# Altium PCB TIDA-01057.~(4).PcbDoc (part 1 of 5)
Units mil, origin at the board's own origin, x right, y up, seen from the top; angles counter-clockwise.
Board outline 4448 x 3930 mil, 4 copper layers (Layer 1 - Top Layer, Layer 2 - GND, Layer 3 - PWR, Layer 4 - Bottom Layer), stack 59.034 mil thick; 537 components, 284 nets, 1540 pads, 770 vias.
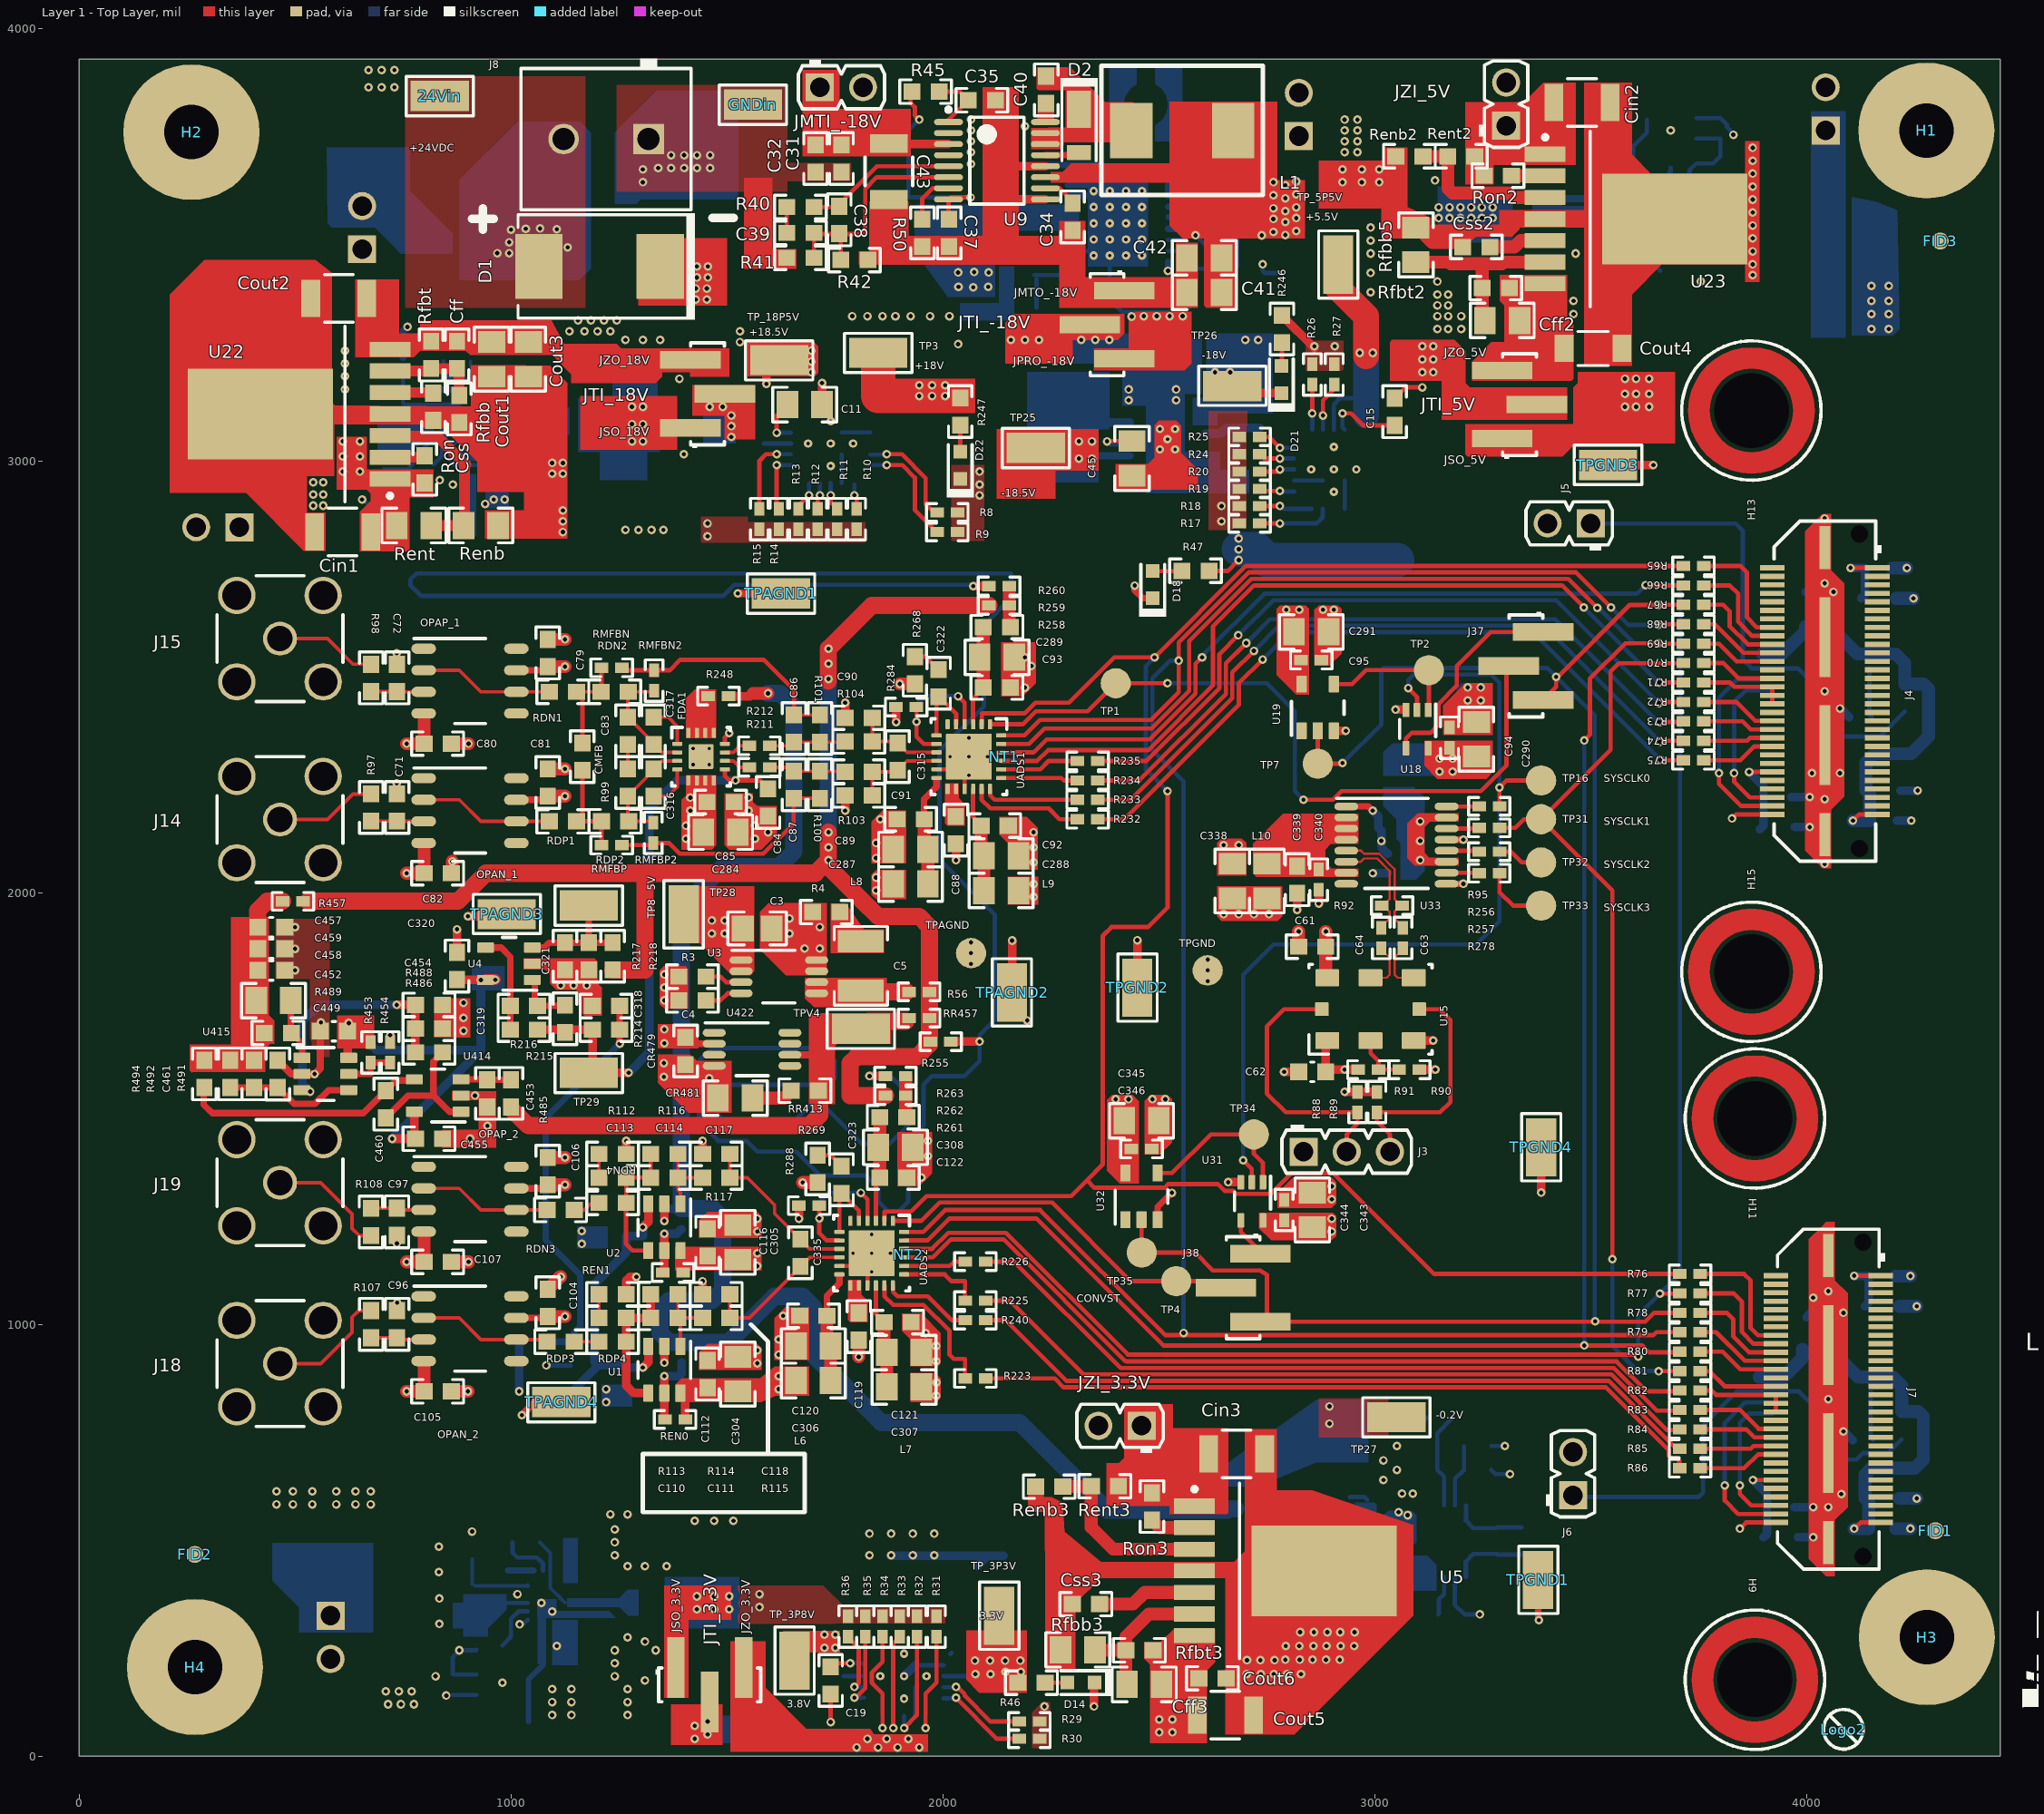
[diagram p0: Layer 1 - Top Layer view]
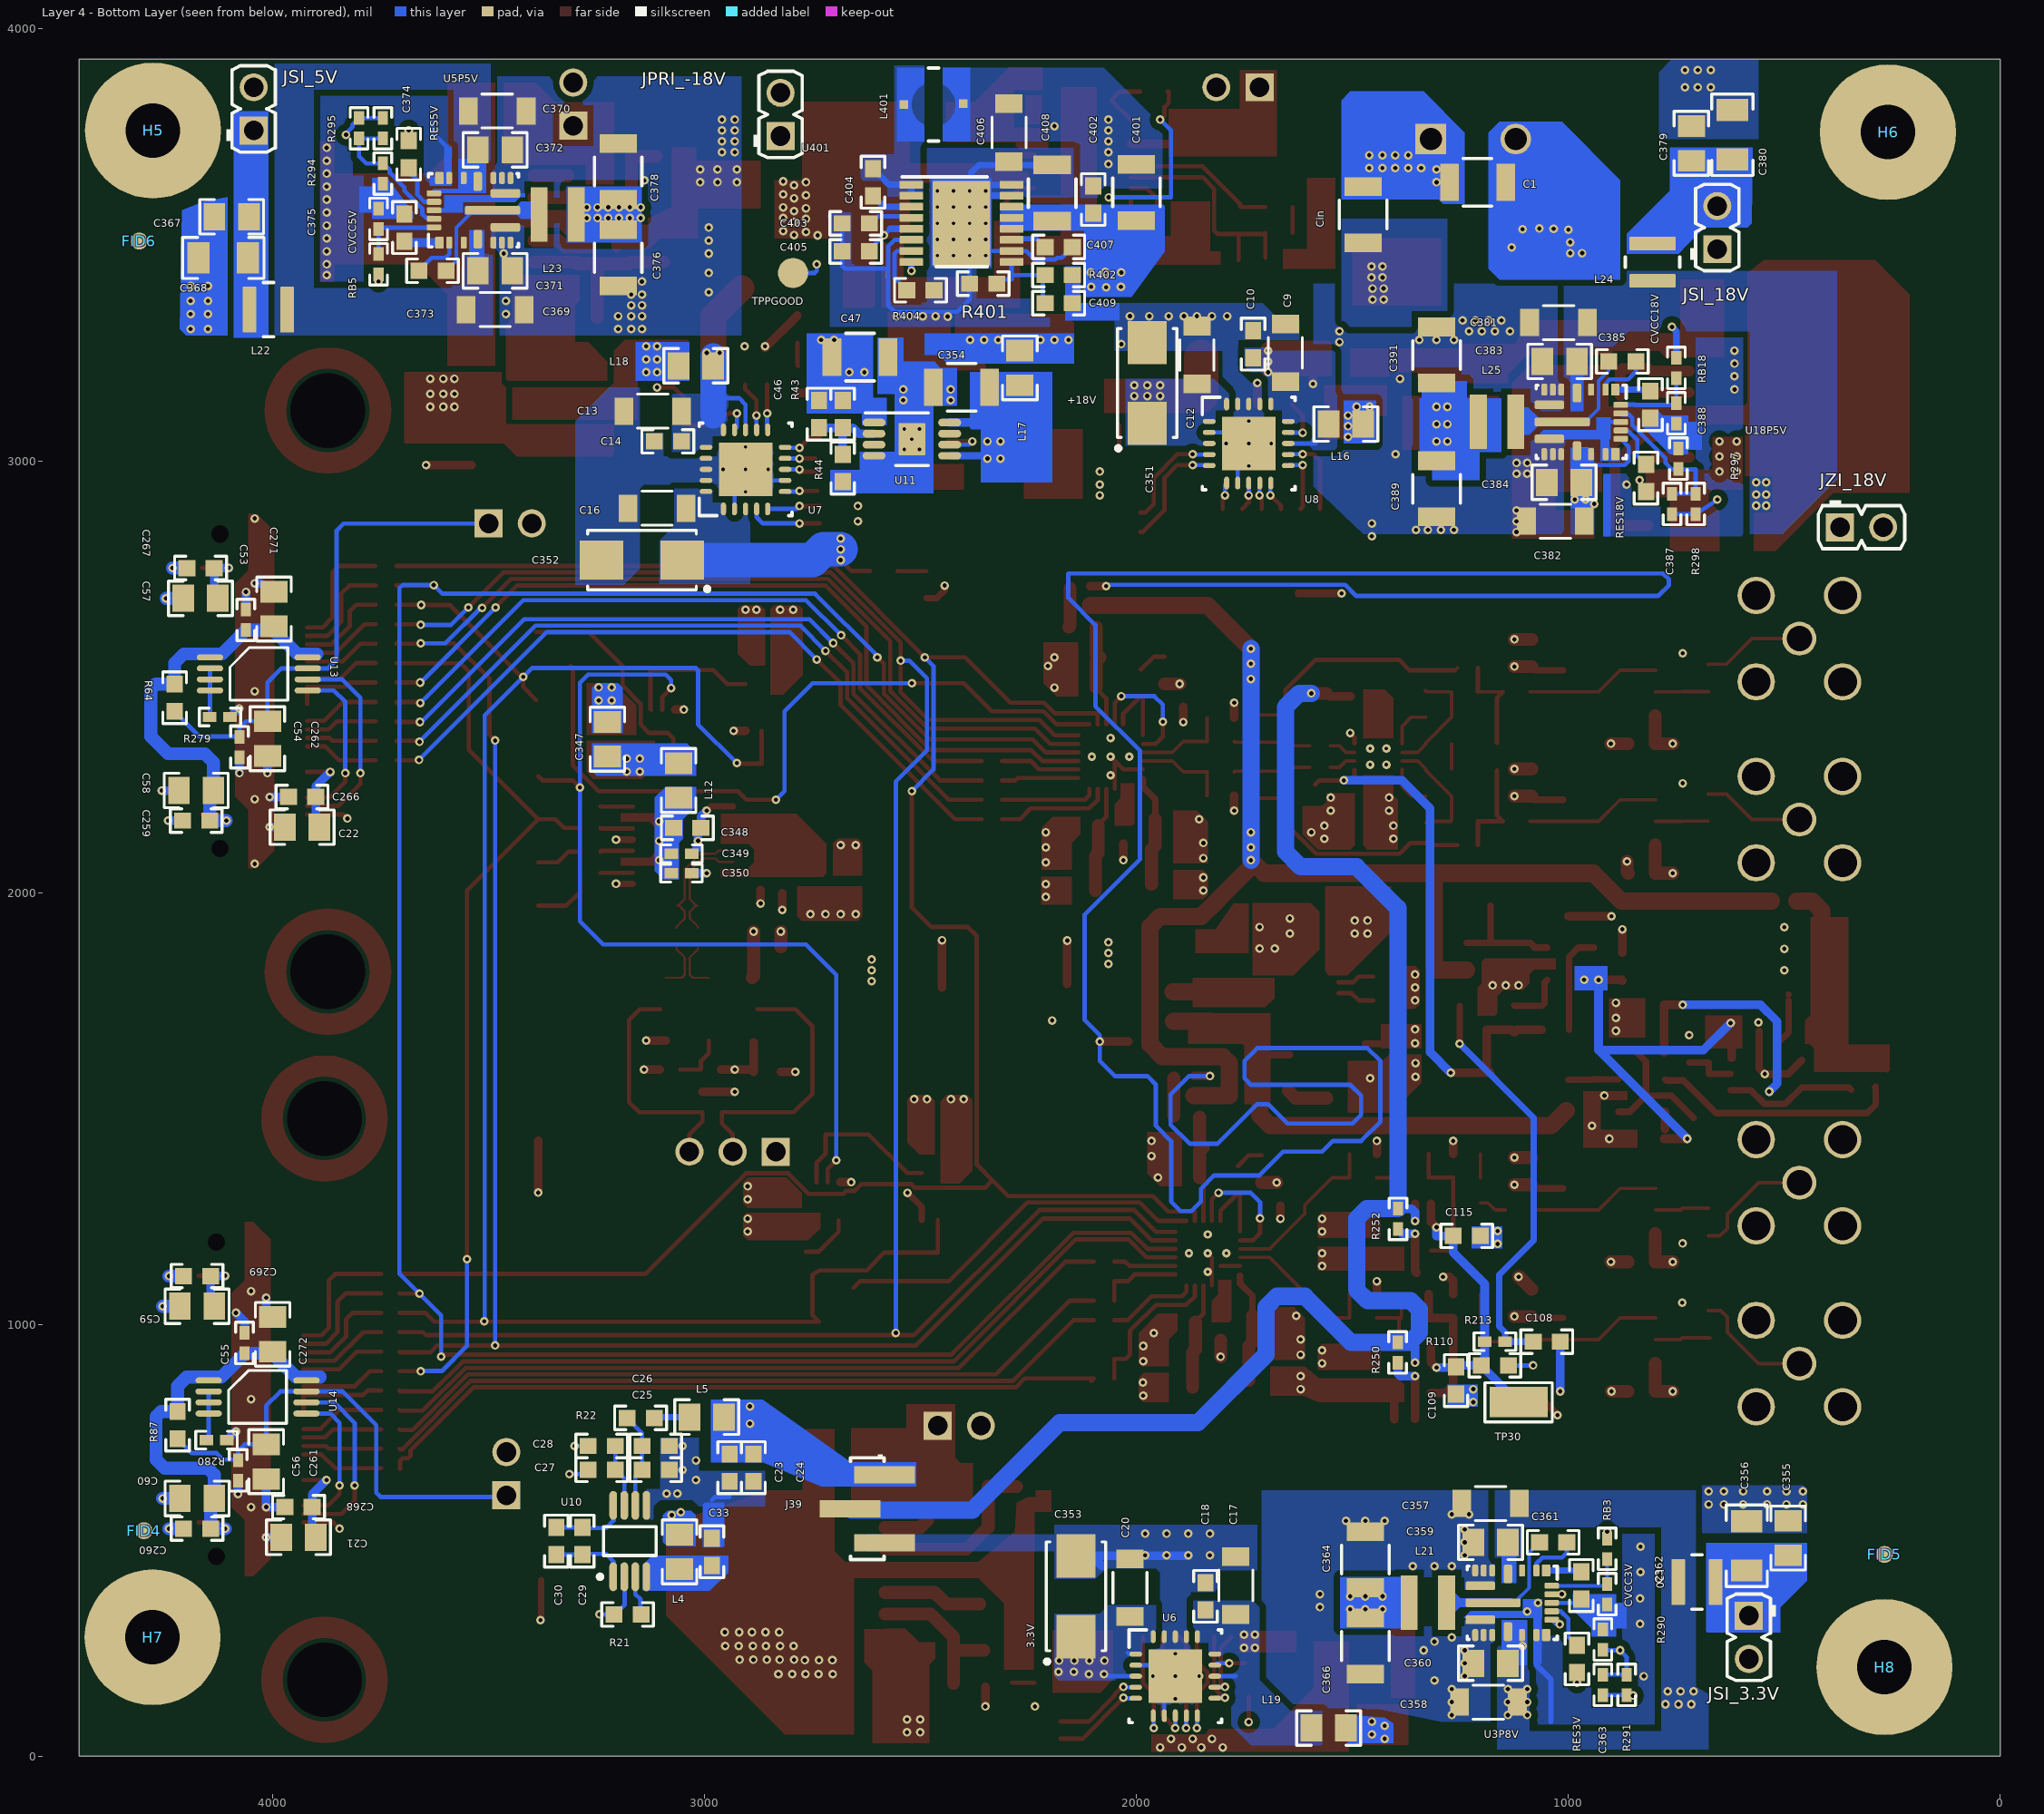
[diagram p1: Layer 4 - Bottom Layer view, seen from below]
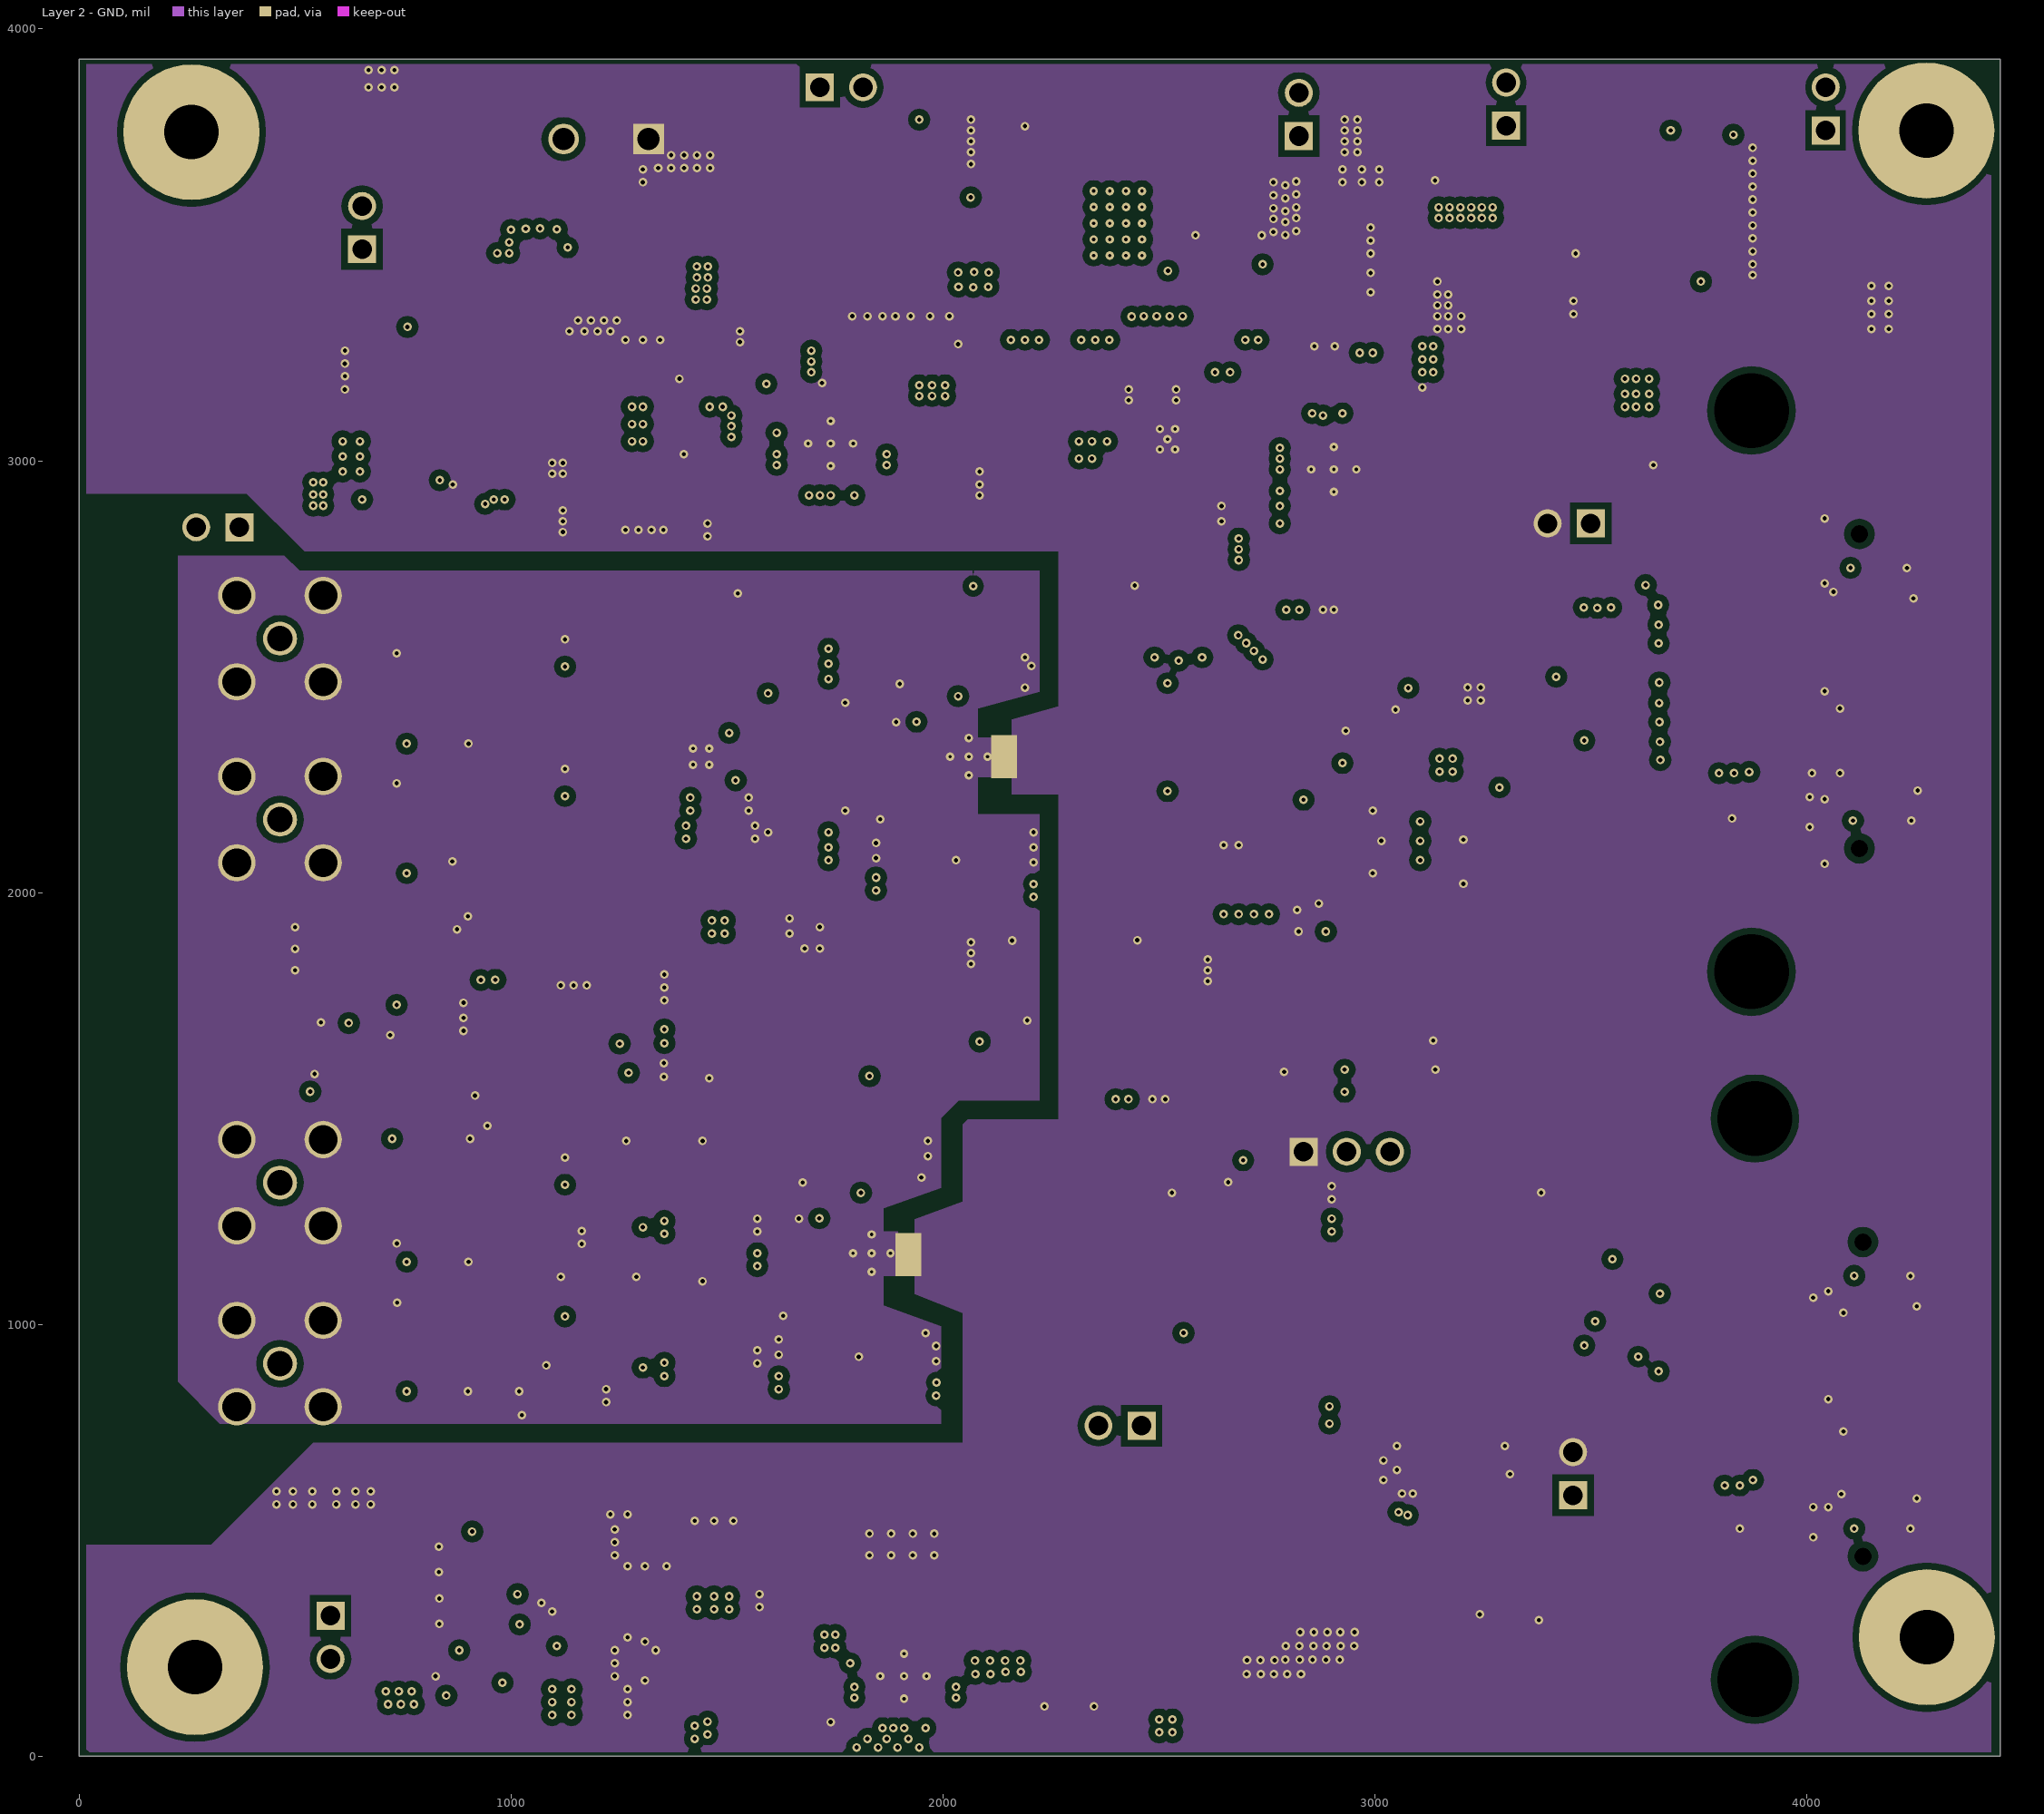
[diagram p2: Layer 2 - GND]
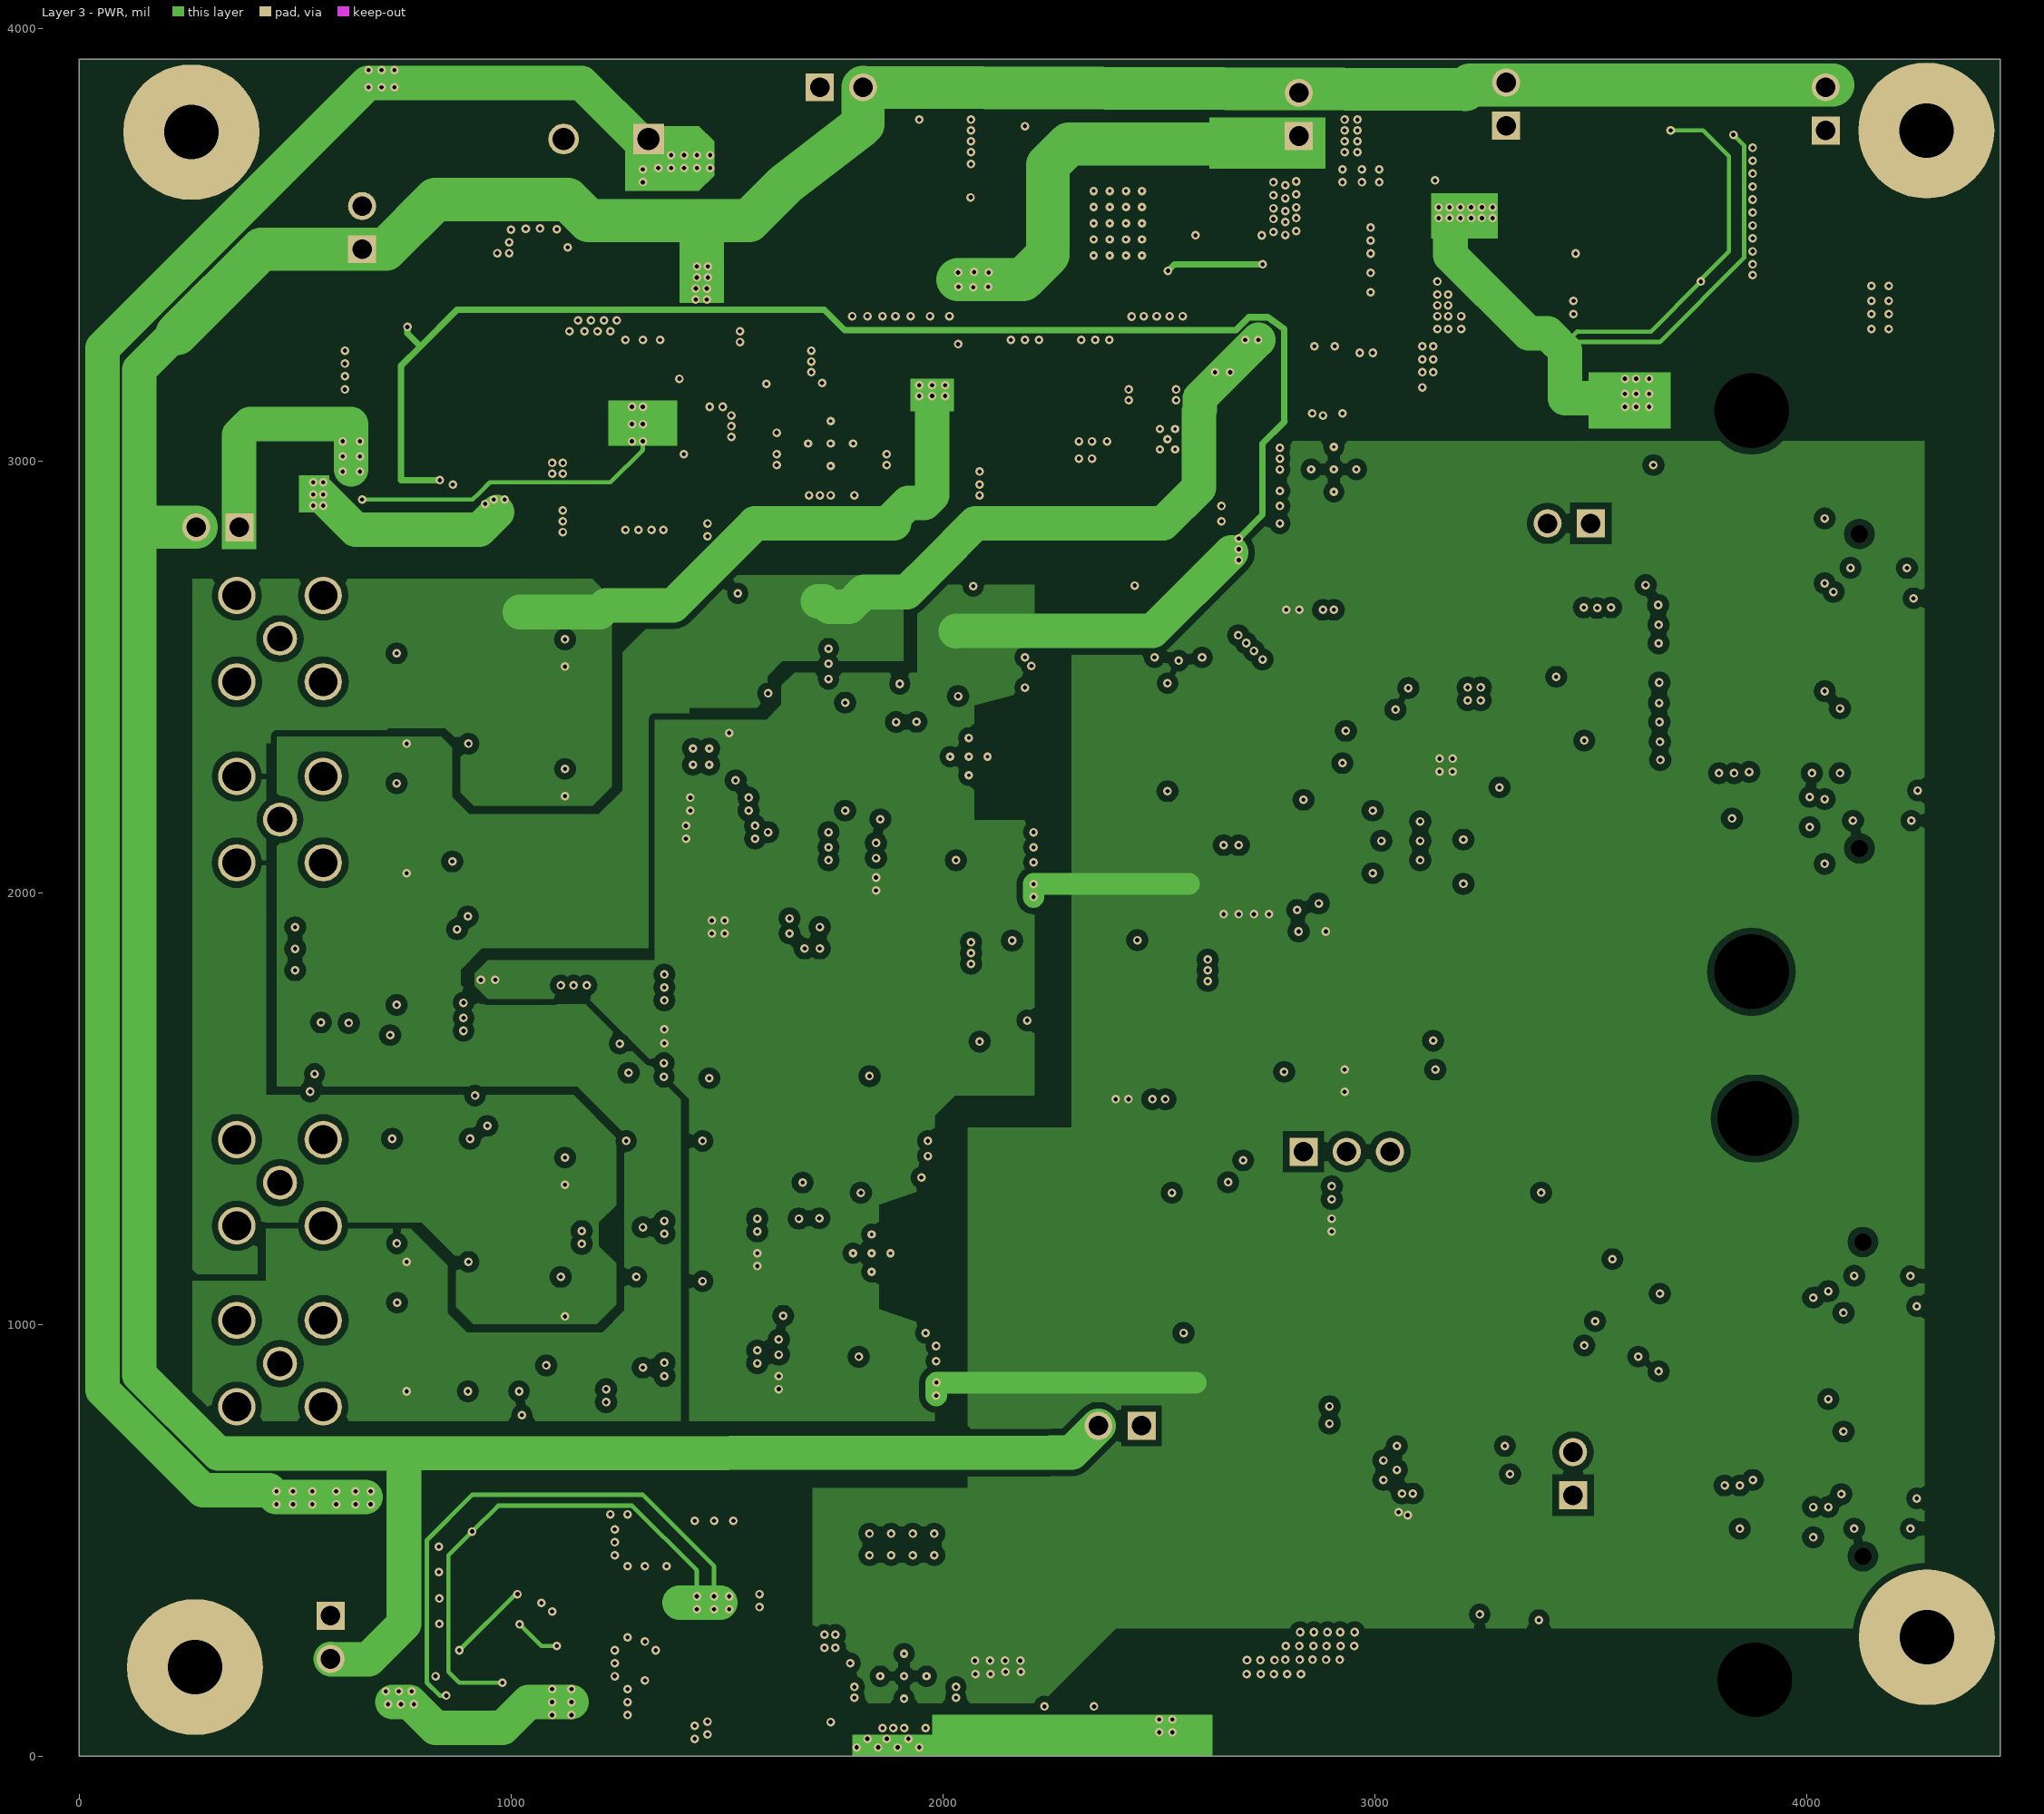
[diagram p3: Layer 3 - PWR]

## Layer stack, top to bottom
Top Solder: solder mask 0.4, Solder Resist, Dk 3.5
Layer 1 - Top Layer: signal copper 1.4
Dielectric 1: prepreg 5.2, 370HR, Dk 4.2
Layer 2 - GND: signal copper 1.417
Dielectric 2: core 43, 370HR, Dk 4.2
Layer 3 - PWR: signal copper 1.417
Dielectric 3: prepreg 5.2, 370HR, Dk 4.2
Layer 4 - Bottom Layer: signal copper 1.4
Bottom Solder: solder mask 0.4, Solder Resist, Dk 3.5

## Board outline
0,0 0,3930 4448,3930 4448,0

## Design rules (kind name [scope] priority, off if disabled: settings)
AcuteAngle [All] p1: minimum=4.50000000000000E+0001 checktracksonly=FALSE
AssemblyTestPointUsage [All] p1: valid=2
Clearance Clearance_Keepouts [((IsTrack Or IsArc) And Not InPoly) And IsFree and IsKeepOut vs ((IsTrack Or IsArc) And Not InPoly) And IsFree and IsKeepOut] p1: gap=0 ignorepadtopadclearanceinfootprint=FALSE
Clearance Clearance_BoardEdge_MountingHoles [OnCopper and InComponentClass('Mounting Holes') vs IsKeepOut] p2: gap=40 ignorepadtopadclearanceinfootprint=FALSE except(0: Arc-Hole Track-Hole SMDPad-Hole THPad-Hole Via-Hole Fill-Hole Poly-Hole Region-Hole Text-Hole)
Clearance Clearance_BoardEdge_Poly [OnCopper and InPoly vs IsKeepOut] p3: gap=25 ignorepadtopadclearanceinfootprint=FALSE except(0: Arc-Hole Track-Hole SMDPad-Hole THPad-Hole Via-Hole Fill-Hole Poly-Hole Region-Hole Text-Hole)
Clearance Clearance_BoardEdge [OnCopper and Not InComponentClass('Logo') and not InComponentClass('FiducialMark') and not InRegion(1000,500,4000,800) and Not IsKeepout vs IsKeepOut] p4: gap=75 ignorepadtopadclearanceinfootprint=FALSE except(0: Arc-Hole Track-Hole SMDPad-Hole THPad-Hole Via-Hole Fill-Hole Poly-Hole Region-Hole Text-Hole)
Clearance Clearance_Poly [InPolygon] p5: gap=15 ignorepadtopadclearanceinfootprint=FALSE except(0: Arc-Hole Track-Hole SMDPad-Hole THPad-Hole Via-Hole Fill-Hole Poly-Hole Region-Hole Text-Hole)
Clearance [All] p6: gap=5 ignorepadtopadclearanceinfootprint=FALSE except(0: Arc-Hole Track-Hole SMDPad-Hole THPad-Hole Via-Hole Fill-Hole Poly-Hole Region-Hole Text-Hole)
ComponentClearance ComponentClearance_MountingHoles_FiducialMarks [InComponentClass('Mounting Holes') vs InComponentClass('FiducialMark')] p1: gap=25 collisioncheckmode=3 verticalgap=10 showdistances=FALSE
ComponentClearance ComponentClearance_Shunt [InComponentClass('Header') vs InComponentClass('Shunt')] p2: gap=0 collisioncheckmode=3 verticalgap=0 showdistances=FALSE
ComponentClearance ComponentClearance_Logo [InComponentClass('Logo')] p3: gap=10 collisioncheckmode=3 verticalgap=10 showdistances=FALSE
ComponentClearance ComponentClearance_ScrewToNut [(HasFootprint('NY PMS 440 0025 PH')) vs (HasFootprint('Keystone_1902C'))] p4: gap=5 collisioncheckmode=3 verticalgap=10 showdistances=FALSE
ComponentClearance ComponentClearance_MountingHoles [InComponentClass('Mounting Holes')] p5: gap=15 collisioncheckmode=3 verticalgap=100000 showdistances=FALSE
ComponentClearance ComponentClearance_SmallPassives [HasFootprint('0201*') or HasFootprint('0402*') or HasFootprint('0508') or HasFootprint('0603*') or HasFootprint('0612') or HasFootprint('0805*') or HasFootprint('0815*') or HasFootprint('0830*') or HasFootprint('1206*') or HasFootprint('1210*') or HasFootprint('1808*') or HasFootprint('1812*') or HasFootprint('1825*') or HasFootprint('2010*') or HasFootprint('2220*') or HasFootprint('2225*') or HasFootprint('2512*') or HasFootprint('2728*') or HasFootprint('3518*') vs HasFootprint('0201*') or HasFootprint('0402*') or HasFootprint('0508') or HasFootprint('0603*') or HasFootprint('0612') or HasFootprint('0805*') or HasFootprint('0815*') or HasFootprint('0830*') or HasFootprint('1206*') or HasFootprint('1210*') or HasFootprint('1808*') or HasFootprint('1812*') or HasFootprint('1825*') or HasFootprint('2010*') or HasFootprint('2220*') or HasFootprint('2225*') or HasFootprint('2512*') or HasFootprint('2728*') or HasFootprint('3518*')] p6: gap=5 collisioncheckmode=3 verticalgap=10 showdistances=FALSE
ComponentClearance ComponentClearance_THtoSMT [IsThruComponent vs IsSMTComponent] p7: gap=10 collisioncheckmode=3 verticalgap=30 showdistances=FALSE
ComponentClearance ComponentClearance_THtoTH [IsThruComponent vs IsThruComponent] p8: gap=75 collisioncheckmode=3 verticalgap=30 showdistances=FALSE
ComponentClearance [All] p9: gap=5 collisioncheckmode=3 verticalgap=10 showdistances=FALSE
DiffPairsRouting [All] p1: maxlimit=20 minlimit=6 mostfreqgap=6 toplayer_minwidth=5 toplayer_maxwidth=5 toplayer_prefwidth=5 midlayer1_minwidth=5 midlayer1_maxwidth=5 midlayer1_prefwidth=5 midlayer2_minwidth=5 midlayer2_maxwidth=5 midlayer2_prefwidth=5 bottomlayer_minwidth=5 bottomlayer_maxwidth=5 bottomlayer_prefwidth=5 maxuncoupledlength=1000
FabricationTestPointUsage TestPointUsage [All] p1: valid=2 allowmultiple=FALSE
FabricationTestpoint Testpoint [All] p1: side=3 testpointundercomponent=TRUE minsize=40 maxsize=100 preferedsize=60 minholesize=0 maxholesize=40 preferedholesize=32 testpointgrid=1 allowsidetop=TRUE allowsidebottom=TRUE usegrid=TRUE gridtolerance=0.01
FanoutControl Fanout_LCC [IsLCC] p1: bgadir=Out bgaviamode=Centered fanoutstyle=Auto fanoutdirection=Alternating viagrid=1 // Fanout_LCC (Default Rule)
FanoutControl Fanout_BGA [IsBGA] p2: bgadir=Out bgaviamode=Centered fanoutstyle=Auto fanoutdirection=Alternating viagrid=1 // Fanout_BGA (Default Rule)
FanoutControl Fanout_Default [All] p4: bgadir=Out bgaviamode=Centered fanoutstyle=Auto fanoutdirection=Alternating viagrid=1 // Fanout_Default (Default Rule)
FanoutControl Fanout_Small [(CompPinCount < 5)] p5: bgadir=Out bgaviamode=Centered fanoutstyle=Auto fanoutdirection=OutThenIn viagrid=1 // Fanout_Small (Default Rule)
HoleSize [All] p1: absolutevalues=TRUE maxlimit=251 minlimit=6 maxpercent=80.000 minpercent=20.000
MinimumAnnularRing MinimumAnnularRing_ThermalPadVias [IsVia and InAnyComponent] p1: minimumring=5.91
MinimumAnnularRing [All] p2: minimumring=5
MinimumSolderMaskSliver MinimumSolderMaskSliver_Logo [InComponentClass('Logo') vs InComponentClass('Logo')] p1: minsoldermaskwidth=0
MinimumSolderMaskSliver [All] p2: minsoldermaskwidth=0
PlaneConnect [All] p1: planeconnectstyle=Direct reliefexpansion=10 reliefentries=4 reliefconductorwidth=10 reliefairgap=10
PolygonConnect PolygonConnect_1 [All vs IsNamedPolygon('AGND_L02_P018')] p1: connectstyle=Direct reliefconductorwidth=10 reliefentries=4 polygonreliefangle="90 Angle" airgapwidth=10
PolygonConnect [All] p2: connectstyle=Direct reliefconductorwidth=10 reliefentries=4 polygonreliefangle="90 Angle" airgapwidth=10
RoutingVias ThermalPadVias [IsVia and InAnyComponent] p1: holewidth=7.87 width=19.68 viastyle="Through Hole" minholewidth=7.87 minwidth=19.68 maxholewidth=12.99 maxwidth=23.62
RoutingVias [All] p2: holewidth=16 width=34 viastyle="Through Hole" minholewidth=7.87 minwidth=20 maxholewidth=40 maxwidth=65
SilkToBoardRegionClearance [Not ((IsComment or IsDesignator) And (Hide <> 'False')) and not InRegion(1000,500,4000,800)] p1:
SilkToSilkClearance SilkToSilkClearance_Pb-FreeLogo [(HasFootprint('Pb-Free_Overlay_Medium') OR HasFootprint('Pb-Free_Overlay_Small')) vs (HasFootprint('Pb-Free_Overlay_Medium') OR HasFootprint('Pb-Free_Overlay_Small'))] p1: silktosilkclearance=0
SilkToSilkClearance [All] p2: silktosilkclearance=0
SilkToSolderMaskClearance SilkToComonentPadClearance [IsPad and InAnycomponent] p1: minsilkscreentomaskgap=0 clearancetoexposedcopper=TRUE
SilkToSolderMaskClearance "Silk to Solder Mask Opening" [All] p2: minsilkscreentomaskgap=0 clearancetoexposedcopper=FALSE
SolderMaskExpansion [All] p1: expansion=1.97
Width Width_DA1_N [InNet('DA1_N')] p1: maxlimit=10 minlimit=5 preferedwidth=5 impedancedriven=TRUE minimp=50.000000 maximp=50.000000 favimp=50.000000
Width Width_DA2_N [InNet('DA2_N')] p2: maxlimit=10 minlimit=5 preferedwidth=5 impedancedriven=TRUE minimp=50.000000 maximp=50.000000 favimp=50.000000
Width Width_DA1_P [InNet('DA1_P')] p3: maxlimit=10 minlimit=5 preferedwidth=5 impedancedriven=TRUE minimp=50.000000 maximp=50.000000 favimp=50.000000
Width Width_DA2_P [InNet('DA2_P')] p4: maxlimit=10 minlimit=5 preferedwidth=5 impedancedriven=TRUE minimp=50.000000 maximp=50.000000 favimp=50.000000
Width Width_VIN+1_P [InNet('VIN+_1_P')] p5: maxlimit=10 minlimit=5 preferedwidth=5 impedancedriven=TRUE minimp=50.000000 maximp=50.000000 favimp=50.000000
Width Width_VIN+2_N [InNet('VIN+_2_N')] p6: maxlimit=10 minlimit=5 preferedwidth=5 impedancedriven=TRUE minimp=50.000000 maximp=50.000000 favimp=50.000000
Width Width_VIN+2_P [InNet('VIN+_2_P')] p7: maxlimit=10 minlimit=5 preferedwidth=5 impedancedriven=TRUE minimp=50.000000 maximp=50.000000 favimp=50.000000
Width Width_VIN+1_N [InNet('VIN+_1_N')] p8: maxlimit=10 minlimit=5 preferedwidth=5 impedancedriven=TRUE minimp=50.000000 maximp=50.000000 favimp=50.000000
Width [All] p9: maxlimit=100 minlimit=5 preferedwidth=10 checkconnectedcopper=TRUE
15 further rules are at their usual default settings.

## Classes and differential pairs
component class "OPA625 ADC Driver_Power_1050": C31 C32 C34 C35 C37 C38 C39 C40 C41 C42 C43 Cff Cff2 Cff3 Cin1 Cin2 Cin3 Cout1 Cout2 Cout3 Cout4 Cout5 Cout6 Css Css2 Css3 D2 JMTI_-18V JZI_3.3V JZI_5V JZI_18V L1 R40 R41 R42 R45 R50 Renb Renb2 Renb3 Rent Rent2 Rent3 Rfbb Rfbb3 Rfbb5 Rfbt Rfbt2 Rfbt3 Ron Ron2 Ron3 U5 U9 U22 U23
component class AssemblyNote: ZZ2 ZZ3 ZZ4
component class FiducialMark: FID1 FID2 FID3 FID4 FID5 FID6
component class "OPA625 ADC Driver_Hardware": FID1 FID2 FID3 FID4 FID5 FID6 H1 H2 H3 H4 H5 H6 H7 H8 H9 H11 H13 H15 Logo1 Logo2 ZZ2 ZZ3 ZZ4
component class Logo: Logo1
component class "Mounting Holes": H1 H2 H3 H4
component class Header: J3 J5 J6 J37 J38 J39 JMTI_-18V JPRI_-18V JSI_3.3V JSI_5V JSI_18V JTI_3.3V JTI_5V JTI_18V JTI_-18V JZI_3.3V JZI_5V JZI_18V
component class "OPA625 ADC Driver_Clock": C61 C62 C63 C64 C338 C339 C340 C347 C348 C349 C350 J3 L10 L12 R88 R89 R90 R91 R92 R95 R256 R257 R278 TP16 TP31 TP32 TP33 U15 U33
component class "OPA625 ADC Driver_Connectors": C21 C22 C53 C54 C55 C56 C57 C58 C59 C60 C259 C260 C261 C262 C266 C267 C268 C269 C271 C272 J4 J5 J6 J7 R64 R65 R66 R67 R68 R69 R70 R71 R72 R73 R74 R75 R76 R77 R78 R79 R80 R81 R82 R83 R84 R85 R86 R87 R279 R280 U13 U14
component class "OPA625 ADC Driver_OPA625 ADC Driver REV1.0": C3 C4 C5 C71 C72 C79 C80 C81 C82 C83 C84 C85 C86 C87 C88 C89 C90 C91 C92 C93 C94 C95 C96 C97 C104 C105 C106 C107 C108 C109 C110 C111 C112 C113 C114 C115 C116 C117 C118 C119 C120 C121 C122 C284 C287 C288 C289 C290 C291 C304 C305 C306 C307 C308 C315 C316 C317 C318 C319 C320 C321 C322 C323 C335 C343 C344 C345 C346 C449 C452 C453 C454 C455 C457 C458 C459 C460 C461 CMFB CR479 CR481 FDA1 J14 J15 J18 J19 J37 J38 L6 L7 L8 L9 OPAN_1 OPAN_2 OPAP_1 OPAP_2 R3 R4 R56 R97 R98 R99 R100 R101 R103 R104 R107 R108 R110 R112 R113 R114 R115 R116 R117 R211 R212 R213 R214 R215 R216 R217 R218 R223 R225 R226 R232 R233 R234 R235 R240 R248 R250 R252 R255 R258 R259 R260 R261 R262 R263 R268 R269 R284 R288 R453 R454 R457 R485 R486 R488 R489 R491 R492 R494 RDN1 RDN2 RDN3 RDN4 RDP1 RDP2 RDP3 RDP4 REN0 REN1 RMFBN RMFBN2 RMFBP RMFBP2 RR413 RR457 TP1 Tp2 TP4 TP7 TP28 TP29 TP30 TP34 TP35 TPAGND TPV4 U1 U2 U3 U4 U18 U19 U31 U32 U414 U415 U422 UADS1 UADS2
component class "OPA625 ADC Driver_Power_1051": 24Vin C1 C9 C10 C11 C12 C13 C14 C15 C16 C17 C18 C19 C20 C23 C24 C25 C26 C27 C28 C29 C30 C33 C45 C46 C47 C351 C352 C353 C354 C355 C356 C357 C358 C359 C360 C361 C362 C363 C364 C366 C367 C368 C369 C370 C371 C372 C373 C374 C375 C376 C378 C379 C380 C381 C382 C383 C384 C385 C387 C388 C389 C391 C401 C402 C403 C404 C405 C406 C407 C408 C409 Cin CVCC3V CVCC5V CVCC18V D1 D14 D18 D21 D22 GNDin J8 J39 JPRI_-18V JSI_3.3V JSI_5V JSI_18V JTI_3.3V JTI_5V JTI_18V JTI_-18V L4 L5 L16 L17 L18 L19 L20 L21 L22 L23 L24 L25 L401 NT1 NT2 R8 R9 R10 R11 R12 R13 R14 R15 R17 R18 R19 R20 R21 R22 R24 R25 R26 R27 R29 R30 R31 R32 R33 R34 R35 R36 R43 R44 R46 R47 R246 R247 R290 R291 R294 R295 R297 R298 R401 R402 R404 RB3 RB5 RB18 RES3V RES5V RES18V TP3 TP8 TP25 TP26 Tp27 TP_3P3V TP_3P8V TP_5P5V TP_18P5V TPAGND1 TPAGND2 TPAGND3 TPAGND4 TPGND TPGND1 TPGND2 TPGND3 TPGND4 TPPGOOD U3P8V U5P5V U6 U7 U8 U10 U11 U18P5V U401
differential pair BCLK0: +BCLK0_P -BCLK0_N
differential pair BCLK1: +BCLK1_P -BCLK1_N

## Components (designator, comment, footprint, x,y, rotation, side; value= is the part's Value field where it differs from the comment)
24Vin "5015" Testpoint_Keystone_Miniature 835,3845 r0 top
C1 "UMK325AB7106KM-T" 1210_280 1210,3645 r0 bottom value=10uF
C3 "GRM21BR71A106KE51L" 0805 1569.79,1916.65 r180 top value=10uF
C4 "GRM188R71A105KA61D" 0603 1420,1750.16 r180 top value=1uF
C5 "GRM32ER71A476KE15L" 1210_270 1810,1830.16 r90 top value=47uF
C9 "C3216X5R1E476M160AC" 1206_190 1655,3250 r90 bottom value=47uF
C10 "CGA3E2X7R2A102K080AA" 0603 1730,3270 r90 bottom value=1000pF
C11 "C2012X7S2A105K125AB" 0805_HV 1680,3130 r0 top value=1uF
C12 "C3216X5R1E476M160AC" 1206_190 1860,3245 r90 bottom value=47uF
C13 "C3216X5R1E476M160AC" 1206_190 3120,3115 r0 bottom value=47uF
C14 "GRM1885C1H102FA01J" 0603 3085,3045 r0 bottom value=1000pF
C15 "GRM188R71E105KA12D" 0603 3046.02,3113.66 r270 top value=1uF
C16 "C3216X5R1E476M160AC" 1206_190 3110,2890 r0 bottom value=47uF
C17 "C3216X5R1E476M160AC" 1206_190 1770,395 r90 bottom value=47uF
C18 "GRM1885C1H102FA01J" 0603 1840,370 r90 bottom value=1000pF
C19 "GRM188R71E105KA12D" 0603 1740,175 r90 top value=1uF
C20 "C3216X5R1E476M160AC" 1206_190 2015,390 r90 bottom value=47uF
C21 "GRM21BR71A106KE51L" 0805_HV 3940.02,506.69 r0 bottom value=10uF
C22 "GRM21BR71A106KE51L" 0805_HV 3932.01,2151.39 r0 bottom value=10uF
C23 "GRM188R61A106ME69D" 0603 2941.79,668 r270 bottom value=10uF
C24 "GRM188R61A106ME69D" 0603 2886.79,668 r270 bottom value=10uF
C25 "GRM188R71E474KA12D" 0603 3113.02,663 r180 bottom value=0.47uF
C26 "GRM188R60J226MEA0D" 0603 3113.02,718 r180 bottom value=22uF
C27 "GRM188R61C104KA01D" 0603 3238.02,663 r0 bottom value=0.1uF
C28 "GRM188R60J226MEA0D" 0603 3238.02,718 r0 bottom value=22uF
C29 "GRM188R61A475MAAJ" 0603 3283.02,498 r90 bottom value=4.7uF
C30 "GRM188R61A224KA01D" 0603 3343.02,498 r90 bottom value=0.22uF
C31 "GCM188R71H224KA64D" 0603 1765,3700 r270 top value=0.22uF
C32 "C1608X7R1H104K080AA" 0603 1705,3700 r270 top value=0.1uF
C33 "GRM188R61A106ME69D" 0603 2983.02,473 r90 bottom value=10uF
C34 "GRM188R71H333KA61D" 0603 2300,3565 r270 top value=0.033uF
C35 "C1608X7R1H104K080AA" 0603 2090,3835 r0 top value=0.1uF
C37 "C0603C911J5GACTU" 0603 2014.22,3527.56 r270 top value=910pF
C38 "CGA3E2C0G1H100D080AA" 0603 1760.02,3557.8 r90 top value=10pF
C39 "GRM1885C1H151JA01D" 0603 1670.02,3527.8 r180 top value=150pF
C40 "GRM188R71H223KA01D" 0603 2239,3859 r270 top value=0.022uF
C41 "C2012X5R1V226M125AC" 0805_HV 2605,3390 r180 top value=22uF
C42 "C2012X7S2A105K125AB" 0805_HV 2605,3470 r180 top value=1uF
C43 "UMK325AB7106KM-T" 1210_280 1875,3670 r270 top value=10uF
C45 "C2012X7S2A105K125AB" 0805_HV 2437.74,3005.49 r270 top value=1uF
C46 "GCM188R71H103KA37D" 0603 2735,3108.05 r270 bottom value=0.01uF
C47 "UMK325AB7106KM-T" 1210_280 2640,3240 r180 bottom value=10uF
C53 "GRM155R71C104KA88D" 0402 4062,2631.4 r270 bottom value=0.1uF
C54 "GRM155R71C104KA88D" 0402 4077.01,2336.39 r90 bottom value=0.1uF
C55 "GRM155R71C104KA88D" 0402 4065.02,956.69 r270 bottom value=0.1uF
C56 "GRM155R71C104KA88D" 0402 4080.03,661.69 r90 bottom value=0.1uF
C57 "GRM21BR71A106KE51L" 0805_HV 4167.01,2681.39 r0 bottom value=10uF
C58 "GRM21BR71A106KE51L" 0805_HV 4177.01,2236.39 r0 bottom value=10uF
C59 "GRM21BR71A106KE51L" 0805_HV 4175.03,1041.69 r0 bottom value=10uF
C60 "GRM21BR71A106KE51L" 0805_HV 4175.03,596.69 r0 bottom value=10uF
C61 "C0603C104J3RACTU" 0603 2855,1874.74 r180 top value=0.1uF
C62 "ZRB18AD71A106KE01L" 0603_120#1 2855,1584.75 r180 top value=10uF
C63 "GRM155R61E104KA87D" 0402 3065,1894.75 r90 top value=0.1uF
C64 "GRM155R61E104KA87D" 0402 3015,1894.75 r90 top value=0.1uF
C71 "GCM1885C2A101JA16D" 0603 736,2197 r270 top value=100pF
C72 "GCM1885C2A101JA16D" 0603 736,2497 r270 top value=100pF
C79 "GRM188R72A104KA35D" 0603 1085,2554.75 r270 top value=0.1uF
C80 "GRM188R72A104KA35D" 0603 830,2344.75 r180 top value=0.1uF
C81 "GRM188R72A104KA35D" 0603 1085,2254.75 r270 top value=0.1uF
C82 "GRM188R72A104KA35D" 0603 829.99,2044.74 r180 top value=0.1uF
C83 "GRM1885C2A680JA01D" 0603 1270,2374.75 r90 top value=68pF
C84 "C0603C104J3RACTU" 0603 1595,2208.75 r270 top value=0.1uF
C85 "C0603C104J3RACTU" 0603 1485,2209.75 r0 top value=0.1uF
C86 "GRM1885C2A391JA01D" 0603 1655,2379.75 r90 top value=390pF
C87 "GRM1885C2A391JA01D" 0603 1655,2249.75 r270 top value=390pF
C88 "GRM188R71A105KA61D" 0603 2030,2144.75 r90 top value=1uF
C89 "C1608C0G2A102J080AA" 0603 1805,2224.75 r180 top value=1000pF
C90 "C1608C0G2A102J080AA" 0603 1805,2404.75 r180 top value=1000pF
C91 "C0603C104J3RACTU" 0603 1925,2169.75 r0 top value=0.1uF
C92 "C0603C104J3RACTU" 0603 2120,2154.75 r0 top value=0.1uF
C93 "C0603C104J3RACTU" 0603 2125,2474.75 r0 top value=0.1uF
C94 "GRM155R71C104KA88D" 0402 3172.81,2358.54 r270 top value=0.1uF
C95 "GRM155R71C104KA88D" 0402 2852.81,2538.54 r180 top value=0.1uF
C96 "GCM1885C2A101JA16D" 0603 736,1000 r270 top value=100pF
C97 "GCM1885C2A101JA16D" 0603 735.7,1237.35 r90 top value=100pF
C104 "GRM188R72A104KA35D" 0603 1085,1049.75 r270 top value=0.1uF
C105 "GRM188R72A104KA35D" 0603 830,844.75 r180 top value=0.1uF
C106 "GRM188R72A104KA35D" 0603 1085,1354.75 r270 top value=0.1uF
C107 "GRM188R72A104KA35D" 0603 830,1144.75 r180 top value=0.1uF
C108 "C0603C104J3RACTU" 0603 1050,959.75 r180 bottom value=0.1uF
C109 "C0603C102J5GAC" 0603 1260,869.75 r270 bottom value=1000pF
C110 "GRM1885C2A131JA01D" 0603 1235,1014.75 r0 top value=130pF
C111 "GRM1885C2A391JA01D" 0603 1355,1014.75 r180 top value=390pF
C112 "C0603C104J3RACTU" 0603 1455,884.75 r270 top value=0.1uF
C113 "GRM1885C2A131JA01D" 0603 1235,1339.75 r180 top value=130pF
C114 "GRM1885C2A391JA01D" 0603 1355,1339.75 r180 top value=390pF
C115 "C0603C102J5GAC" 0603 1235,1204.75 r180 bottom value=1000pF
C116 "C0603C104J3RACTU" 0603 1455,1189.75 r270 top value=0.1uF
C117 "C1608C0G2A102J080AA" 0603 1475,1394.75 r180 top value=1000pF
C118 "C1608C0G2A102J080AA" 0603 1475,1069.75 r180 top value=1000pF
C119 "GRM188R71A105KA61D" 0603 1805,994.75 r270 top value=1uF
C120 "C0603C104J3RACTU" 0603 1700,1019.75 r0 top value=0.1uF
C121 "C0603C104J3RACTU" 0603 1895,1004.75 r0 top value=0.1uF
C122 "C0603C104J3RACTU" 0603 1885,1339.75 r0 top value=0.1uF
C259 "C0603C104J3RACTU" 0603 4177.01,2166.39 r0 bottom value=0.1uF
C260 "C0603C104J3RACTU" 0603 4175.03,526.69 r0 bottom value=0.1uF
C261 "GRM21BR71A106KE51L" 0805_HV 4015.02,681.69 r270 bottom value=10uF
C262 "GRM21BR71A106KE51L" 0805_HV 4012.01,2356.39 r270 bottom value=10uF
C266 "C0603C104J3RACTU" 0603 3932.01,2221.39 r0 bottom value=0.1uF
C267 "C0603C104J3RACTU" 0603 4167.01,2751.39 r0 bottom value=0.1uF
C268 "C0603C104J3RACTU" 0603 3940.02,576.69 r0 bottom value=0.1uF
C269 "C0603C104J3RACTU" 0603 4175.03,1111.71 r0 bottom value=0.1uF
C271 "GRM21BR71A106KE51L" 0805_HV 3997,2656.4 r90 bottom value=10uF
C272 "GRM21BR71A106KE51L" 0805_HV 4000.02,976.69 r90 bottom value=10uF
C284 "GRM21BR71A106KE51L" 0805_HV 1485,2139.75 r0 top value=10uF
C287 "GRM21BR71A106KE51L" 0805_HV 1925,2099.75 r180 top value=10uF
C288 "GRM21BR71A106KE51L" 0805_HV 2135,2084.75 r0 top value=10uF
C289 "GRM21BR71A106KE51L" 0805_HV 2125,2544.75 r0 top value=10uF
C290 "GRM21BR71A106KE51L" 0805_HV 3235,2355.04 r90 top value=10uF
C291 "GRM21BR71A106KE51L" 0805_HV 2852.81,2603.54 r180 top value=10uF
C304 "GRM21BR71A106KE51L" 0805_HV 1525,884.75 r90 top value=10uF
C305 "GRM21BR71A106KE51L" 0805_HV 1525,1189.75 r90 top value=10uF
C306 "GRM21BR71A106KE51L" 0805_HV 1700,949.75 r180 top value=10uF
C307 "GRM21BR71A106KE51L" 0805_HV 1910,934.75 r0 top value=10uF
C308 "GRM21BR71A106KE51L" 0805_HV 1890,1409.75 r0 top value=10uF
C315 "C1608C0G2A102J080AA" 0603 1895,2314.75 r90 top value=1000pF
C316 "C1608C0G2A102J080AA" 0603 1330,2254.75 r90 top value=1000pF
C317 "C1608C0G2A102J080AA" 0603 1330,2374.75 r270 top value=1000pF
C318 "GRM188R71E105KA12D" 0603 1220,1737.38 r180 top value=1uF
C319 "GRM188R71E105KA12D" 0603 1030,1737.38 r180 top value=1uF
C320 "C0603C104J3RACTU" 0603 875,1829.75 r270 top value=0.1uF
C321 "GRM188R71E105KA12D" 0603 1125,1852.38 r270 top value=1uF
C322 "C1608X5R1A226M080AC" 0603 1990,2484.75 r90 top value=22uF
C323 "C1608X5R1A226M080AC" 0603 1765,1334.75 r90 top value=22uF
C335 "CGA3E2C0G1H103J080AA" 0603 1670,1165.75 r90 top value=0.01uF
C338 "GRM21BR71A106KE51L" 0805_HV 2670,2026.65 r90 top value=10uF
C339 "GRM188R71E105KA12D" 0603 2820,2029.75 r270 top value=1uF
C340 "GRM155R71C104KA88D" 0402 2870,2029.75 r270 top value=0.1uF
C343 "GRM21BR71A106KE51L" 0805_HV 2855.21,1264.75 r90 top value=10uF
C344 "GRM155R71C104KA88D" 0402 2790.21,1264.75 r270 top value=0.1uF
C345 "GRM21BR71A106KE51L" 0805_HV 2459.83,1471.28 r180 top value=10uF
C346 "GRM155R71C104KA88D" 0402 2459.83,1406.28 r180 top value=0.1uF
C347 "GRM21BR71A106KE51L" 0805_HV 3225,2355.04 r90 bottom value=10uF
C348 "GRM188R71E105KA12D" 0603 3040,2149.75 r180 bottom value=1uF
C349 "GRM155R71C104KA88D" 0402 3053.55,2089.75 r180 bottom value=0.1uF
C350 "GRM155R71C104KA88D" 0402 3053.55,2044.75 r180 bottom value=0.1uF
C351 "293D475X9025C2TE3" 6032-28 1975,3180 r90 bottom value=4.7uF
C352 "293D475X9025C2TE3" 6032-28 3145,2770 r0 bottom value=4.7uF
C353 "293D475X9025C2TE3" 6032-28 2140,370 r90 bottom value=4.7uF
C354 "UMK325AB7106KM-T" 1210_280 2405,3170 r0 bottom value=10uF
C355 "C2012X7R2A104K125AA" 0805_HV 491,505 r90 bottom value=0.1uF
C356 "C3216X7R1V475K085AC" 1206 587,487 r90 bottom value=4.7uF
C357 "GRM31CR71E106KA12L" 1206_180 1180,585 r0 bottom value=10uF
C358 "GRM31CR71E106KA12L" 1206_180 1185,125 r0 bottom value=10uF
C359 "C2012X7R2A104K125AA" 0805_HV 1180,495 r0 bottom value=0.1uF
C360 "C2012X7R2A104K125AA" 0805_HV 1180,215 r0 bottom value=0.1uF
C361 "GCM188R71E474KA64D" 0603 1035,495 r0 bottom value=0.47uF
C362 "C1005X6S1H104K050BB" 0402 910,375 r270 bottom value=0.1uF
C363 "C0402C101J3GACTU" 0402 920,165 r270 bottom value=100pF
C364 "CGA6P1X7R1C226M250AC" 1210_280 1470,455 r90 bottom value=22uF
C366 "CGA6P1X7R1C226M250AC" 1210_280 1470,255 r270 bottom value=22uF
C367 "C2012X7R2A104K125AA" 0805_HV 4095,3565 r0 bottom value=0.1uF
C368 "C3216X7R1V475K085AC" 1206 4114.41,3470 r0 bottom value=4.7uF
C369 "GRM31CR71E106KA12L" 1206_180 3485,3350 r180 bottom value=10uF
C370 "GRM31CR71E106KA12L" 1206_180 3480,3810 r180 bottom value=10uF
C371 "C2012X7R2A104K125AA" 0805_HV 3485,3440 r180 bottom value=0.1uF
C372 "C2012X7R2A104K125AA" 0805_HV 3485,3720 r180 bottom value=0.1uF
C373 "GCM188R71E474KA64D" 0603 3630,3440 r180 bottom value=0.47uF
C374 "C0402C101J3GACTU" 0402 3745,3770 r90 bottom value=100pF
C375 "C1005X6S1H104K050BB" 0402 3755,3560 r90 bottom value=0.1uF
C376 "CGA6P1X7R1C226M250AC" 1210_280 3200,3470 r270 bottom value=22uF
C378 "CGA6P1X7R1C226M250AC" 1210_280 3200,3670 r90 bottom value=22uF
C379 "C2012X7R2A104K125AA" 0805_HV 715,3735 r90 bottom value=0.1uF
C380 "C3216X7R1V475K085AC" 1206 620,3755 r90 bottom value=4.7uF
C381 "GRM31CR71E106KA12L" 1206_180 1022.8,3320 r0 bottom value=10uF
C382 "GRM31CR71E106KA12L" 1206_180 1030,2860 r0 bottom value=10uF
C383 "C2012X7R2A104K125AA" 0805_HV 1020,3230 r0 bottom value=0.1uF
C384 "C2012X7R2A104K125AA" 0805_HV 1010,2950 r0 bottom value=0.1uF
C385 "GCM188R71E474KA64D" 0603 875,3230 r0 bottom value=0.47uF
C387 "C0402C101J3GACTU" 0402 760,2900 r270 bottom value=100pF
C388 "C1005X6S1H104K050BB" 0402 750,3110 r270 bottom value=0.1uF
C389 "UMK325AB7106KM-T" 1210_280 1305,2935 r270 bottom value=10uF
C391 "UMK325AB7106KM-T" 1210_280 1305,3245 r90 bottom value=10uF
C401 "C3225X7S1H106K250AB" 1210_280 2000,3621.5 r90 bottom value=10uF
C402 "C1608X5R1H104K080AA" 0603 2100,3605 r90 bottom value=0.1uF
C403 "GRM188R61E475KE11D" 0603 2650,3550 r0 bottom value=4.7uF
C404 "C1608X5R1H474K080AB" 0603 2610,3645 r90 bottom value=0.47uF
C405 "C1608X7R1V105K080AC" 0603 2650,3485 r0 bottom value=1uF
C406 "C3216X5R1V226M160AC" 1206_180 2295,3760 r270 bottom value=22uF
C407 "C0603C223K3RACTU" 0603 2180,3495 r180 bottom value=0.022uF
C408 "UMK325AB7106KM-T" 1210_280 2195,3620 r90 bottom value=10uF
C409 "885012006057" 0603 2180,3365 r0 bottom value=100pF
C449 "ZRB18AD71A106KE01L" 0603_120#1 589.83,1679.02 r0 top value=10uF
C452 "0805YC224JAT2A" 0805_HV 450,1749.75 r0 top value=0.22uF
C453 "GRM188R71E105KA12D" 0603 945,1534.75 r270 top value=1uF
C454 "C0603C104J3RACTU" 0603 810,1739.75 r0 top value=0.1uF
C455 "C0603C104J3RACTU" 0603 810,1429.75 r180 top value=0.1uF
C457 "ZRB18AD71A106KE01L" 0603_120#1 445,1919.75 r0 top value=10uF
C458 "ZRB18AD71A106KE01L" 0603_120#2 445,1814.75 r0 top value=10uF
C459 "ZRB18AD71A106KE01L" 0603_120#1 445,1869.75 r0 top value=10uF
C460 "C0603C104J3RACTU" 0603 710,1509.75 r90 top value=0.1uF
C461 "C0603C100F5GAC7867" 0603 404.7,1580 r270 top value=10pF
Cff "C1608X7R2A223K080AA" 0603 875,3245 r270 top value=0.022uF
Cff2 "08055C223KAT2A" 0805_HV 3295,3325 r180 top value=0.022uF
Cff3 "08055C223KAT2A" 0805_HV 2466,166 r180 top value=0.022uF
Cin "UMK325AB7106KM-T" 1210_280 1475,3570 r90 bottom value=10uF
Cin1 "UMK325AB7106KM-T" 1210_280 610,2835 r180 top value=10uF
Cin2 "UMK325AB7106KM-T" 1210_280 3479.71,3829.96 r0 top value=10uF
Cin3 "UMK325AB7106KM-T" 1210_280 2680,700 r0 top value=10uF
CMFB "GRM1885C2A680JA01D" 0603 1165,2314.75 r90 top value=68pF
Cout1 "C2012JB1V226M125AC" 0805_HV 955,3235 r270 top value=22uF
Cout2 "UMK325AB7106KM-T" 1210_280 601,3376 r180 top value=10uF
Cout3 "C2012X7S2A105K125AB" 0805_HV 1040,3235 r270 top value=1uF
Cout4 "C3216X5R1E476M160AC" 1206_190 3505,3260 r0 top value=47uF
Cout5 "C3225X6S0J107M250AC" 1210_280 2654,95 r0 top value=100uF
Cout6 "C0603C105K3RACTU" 0603 2624,180 r0 top value=1uF
CR479 "GRM188R71E105KA12D" 0603 1404,1633 r270 top value=1uF
CR481 "GRM21BR71A106KE51L" 0805_HV 1519,1524 r180 top value=10uF
Css "CGA3E2X7R2A472K080AA" 0603 820,3125 r90 top value=4700pF
Css2 "GRM188R70J103KA01D" 0603 3235,3495 r180 top value=0.01uF
Css3 "GRM188R70J103KA01D" 0603 2331,352 r180 top value=0.01uF
CVCC3V "GCM188R70J225KE22D" 0603 970,395 r270 bottom value=2.2uF
CVCC5V "GCM188R70J225KE22D" 0603 3695,3540 r90 bottom value=2.2uF
CVCC18V "GCM188R70J225KE22D" 0603 810,3130 r270 bottom value=2.2uF
D1 "MBRS4201T3G" SMC 1205,3450 r180 top value=200V
D2 "DFLS1100-7" PowerDI123 2315,3764 r270 top value=100V
D14 "150060RS75000" WL-SMCW_RED 2320,170 r180 top value=Red
D18 "150060RS75000" WL-SMCW_RED 2486,2713 r90 top value=Red
D21 "150060RS75000" WL-SMCW_RED 2783.32,3188.24 r90 top value=Red
D22 "150060RS75000" WL-SMCW_RED 2040,2990 r90 top value=Red
FDA1 "THS4561IRGTR" RGT0016A 1440,2314.75 r0 top
FID1 "Fiducial" Fiducial10-20 4298,522 r0 top
FID2 "Fiducial" Fiducial10-20 268,467 r0 top
FID3 "Fiducial" Fiducial10-20 4309,3509 r0 top
FID4 "Fiducial" Fiducial10-20 4298,522 r180 bottom
FID5 "Fiducial" Fiducial10-20 268,467 r180 bottom
FID6 "Fiducial" Fiducial10-20 4309,3509 r180 bottom
GNDin "5015" Testpoint_Keystone_Miniature 1560,3825 r0 top
H1 "NY PMS 440 0025 PH" "NY PMS 440 0025 PH" 4277,3765 r0 top locked
H2 "NY PMS 440 0025 PH" "NY PMS 440 0025 PH" 260,3761 r0 top locked
H3 "NY PMS 440 0025 PH" "NY PMS 440 0025 PH" 4278,275 r0 top locked
H4 "NY PMS 440 0025 PH" "NY PMS 440 0025 PH" 268,206 r0 top locked
H5 "1902C" Keystone_1902C 4277,3765 r180 bottom locked
H6 "1902C" Keystone_1902C 259.47,3761 r180 bottom locked
H7 "1902C" Keystone_1902C 4278,275 r180 bottom locked
H8 "1902C" Keystone_1902C 268,206 r180 bottom locked
H9 "9774050360R" Wurth_WA-SMSI 3880.02,176.69 r180 top
H11 "9774050360R" Wurth_WA-SMSI 3880.02,1476.69 r180 top
H13 "9774050360R" Wurth_WA-SMSI 3872.01,3116.39 r180 top
H15 "9774050360R" Wurth_WA-SMSI 3872.01,1816.39 r180 top
J3 "61300311121" WURTH_61300311121 2935,1399.75 r0 top
J4 "QTH-030-01-L-D-A" Samtec_QTH-030-01-x-D-A 4042.01,2466.39 r270 top
J5 "61300211121" WURTH_61300211121 3450,2855 r180 top
J6 "61300211121" WURTH_61300211121 3459,654 r90 top
J7 "QTH-030-01-L-D-A" Samtec_QTH-030-01-x-D-A 4050.02,826.69 r270 top
J8 "691213710002" Wurth_691213710002 1220,3745 r180 top
J14 "901-144-8RFX" Amphenol_901-144-8RFX 465,2169 r90 top
J15 "901-144-8RFX" Amphenol_901-144-8RFX 465,2588 r90 top
J18 "901-144-8RFX" Amphenol_901-144-8RFX 465,909 r90 top
J19 "901-144-8RFX" Amphenol_901-144-8RFX 465,1328 r90 top
J37 "TMM-103-01-G-S-SM" Samtec_TMM-103-01-x-S-SM 3350,2524.75 r270 top
J38 "TMM-103-01-G-S-SM" Samtec_TMM-103-01-x-S-SM 2695,1084.75 r270 top
J39 "TMM-103-01-G-S-SM" Samtec_TMM-103-01-x-S-SM 2623.02,573 r270 bottom
JMTI_-18V "61300211121" WURTH_61300211121 1765,3865 r0 top
JPRI_-18V "61300211121" WURTH_61300211121 2824,3802 r90 bottom
JSI_3.3V "61300211121" WURTH_61300211121 582,275 r270 bottom
JSI_5V "61300211121" WURTH_61300211121 4044,3815 r90 bottom
JSI_18V "61300211121" WURTH_61300211121 655,3540 r90 bottom
JTI_3.3V "TMM-103-01-G-S-SM" Samtec_TMM-103-01-x-S-SM 1460,165 r0 top
JTI_5V "TMM-103-01-G-S-SM" Samtec_TMM-103-01-x-S-SM 3335,3130 r90 top
JTI_18V "TMM-103-01-G-S-SM" Samtec_TMM-103-01-x-S-SM 1455,3155 r90 top
JTI_-18V "TMM-103-01-G-S-SM" Samtec_TMM-103-01-x-S-SM 2380,3315 r270 top
JZI_3.3V "61300211121" WURTH_61300211121 2410,765 r180 top
JZI_5V "61300211121" WURTH_61300211121 3304,3826 r90 top
JZI_18V "61300211121" WURTH_61300211121 321,2846 r180 bottom
L1 "DR73-331-R" DR73 2554,3765 r0 top value=330uH
L4 "MPZ2012S601A" 0805_HV 3058.02,473 r90 bottom value="600 ohm"
L5 "MPZ2012S601A" 0805_HV 2995,785 r0 bottom value="600 ohm"
L6 "MPZ2012S601A" 0805_HV 1700,869.75 r0 top value="600 ohm"
L7 "MPZ2012S601A" 0805_HV 1910,854.75 r180 top value="600 ohm"
L8 "MPZ2012S601A" 0805_HV 1925,2019.75 r0 top value="600 ohm"
L9 "MPZ2012S601A" 0805_HV 2135,2004.75 r180 top value="600 ohm"
L10 "MPZ2012S601A" 0805_HV 2750,2026.65 r270 top value="600 ohm"
L12 "MPZ2012S601A" 0805_HV 3060,2259.75 r90 bottom value="600 ohm"
L16 "MPZ2012S601A" 0805_HV 1515,3085 r180 bottom value="600 ohm"
L17 "MPZ2012S601A" 0805_HV 2270,3215 r90 bottom value="600 ohm"
L18 "MPZ2012S601A" 0805_HV 3020,3220 r180 bottom value="600 ohm"
L19 "MPZ2012S601A" 0805_HV 1555,65 r0 bottom value="600 ohm"
L20 "NR3015T3R3M" NR3015 702,403 r0 bottom value=3.3uH
L21 "744025006" WE-TPC_2828 1325,355 r0 bottom value=6.8uH
L22 "NR3015T3R3M" NR3015 4010,3350 r180 bottom value=3.3uH
L23 "744025006" WE-TPC_2828 3340,3570 r180 bottom value=6.8uH
L24 "NR3015T3R3M" NR3015 805,3460 r270 bottom value=3.3uH
L25 "744025006" WE-TPC_2828 1165,3090 r0 bottom value=6.8uH
L401 "744031680" WE-TPC_3816 2470,3825 r180 bottom value=68uH
Logo1 "Texas Instruments" TI_Stacked_Overlay_Small 4598,481 r90 top
Logo2 "Pb-Free Symbol" Pb-Free_Overlay_Small 4085,62 r0 top
NT1 "Net-Tie" Net-Tie_50milWide_30milLong 2141.69,2314.75 r0 top net-tie
NT2 "Net-Tie" Net-Tie_50milWide_30milLong 1920,1161 r0 top net-tie
OPAN_1 "OPA827AIDR" D0008A_N 904.99,2189.74 r0 top
OPAN_2 "OPA827AIDR" D0008A_N 905,989.75 r0 top
OPAP_1 "OPA827AIDR" D0008A_N 905,2489.75 r0 top
OPAP_2 "OPA827AIDR" D0008A_N 905,1289.75 r0 top
R3 "ERJ-3RQFR22V" 0603 1420,1805.16 r0 top value=0.22
R4 "ERJ-3RQFR22V" 0603 1730,1954.75 r180 top value=0.22
R8 "ERJ-2GE0R00X" 0402 2010,2880 r180 top value=0
R9 "ERJ-2GE0R00X" 0402 2010,2835 r180 top value=0
R10 "ERJ-2GE0R00X" 0402 1800,2865 r90 top value=0
R11 "ERJ-2GE0R00X" 0402 1755,2865 r90 top value=0
R12 "ERJ-2GE0R00X" 0402 1710,2865 r90 top value=0
R13 "ERJ-2GE0R00X" 0402 1665,2865 r90 top value=0
R14 "ERJ-2GE0R00X" 0402 1620,2865 r90 top value=0
R15 "ERJ-2GE0R00X" 0402 1575,2865 r90 top value=0
R17 "ERJ-2GE0R00X" 0402 2710,2855 r0 top value=0
R18 "ERJ-2GE0R00X" 0402 2710,2895 r0 top value=0
R19 "ERJ-2GE0R00X" 0402 2710,2935 r0 top value=0
R20 "ERJ-2GE0R00X" 0402 2710,2975 r0 top value=0
R21 "CRCW06030000Z0EA" 0603 3178.02,328 r180 bottom value=0
R22 "RT0603DRE074R7L" 0603 3148.02,783 r180 bottom value=4.70
R24 "ERJ-2GE0R00X" 0402 2710,3015 r0 top value=0
R25 "ERJ-2GE0R00X" 0402 2710,3055 r0 top value=0
R26 "ERJ-2GE0R00X" 0402 2855,3200 r270 top value=0
R27 "ERJ-2GE0R00X" 0402 2906,3200 r270 top value=0
R29 "ERJ-2GE0R00X" 0402 2200,80 r180 top value=0
R30 "ERJ-2GE0R00X" 0402 2200,40 r180 top value=0
R31 "ERJ-2GE0R00X" 0402 1985,300 r270 top value=0
R32 "ERJ-2GE0R00X" 0402 1940,300 r270 top value=0
R33 "ERJ-2GE0R00X" 0402 1900,300 r270 top value=0
R34 "ERJ-2GE0R00X" 0402 1860,300 r270 top value=0
R35 "ERJ-2GE0R00X" 0402 1820,300 r270 top value=0
R36 "ERJ-2GE0R00X" 0402 1780,300 r270 top value=0
R40 "RT0603BRD07215KL" 0603 1670.02,3587.8 r180 top value=215k
R41 "RG1608P-2322-B-T5" 0603 1670,3470 r180 top value=23.2k
R42 "RG1608P-1651-B-T5" 0603 1795,3465 r180 top value=1.65k
R43 "RG1608P-3092-B-T5" 0603 2680,3108.05 r90 bottom value=30.9k
R44 "RT0603BRD072K15L" 0603 2680,2983.05 r90 bottom value=2.15k
R45 "RT0603BRD0752K3L" 0603 1960,3855 r180 top value=52.3k
R46 "RC0603JR-07910RL" 0603 2205,170 r180 top value=910
R47 "RT0603BRD0718KL" 0603 2585,2745 r0 top value=18.0k
R50 "RG1608P-203-B-T5" 0603 1952.22,3527.56 r90 top value=20.0k
R56 "ERJ-2GE0R00X" 0402 1945,1769.75 r0 top value=0
R64 "CRCW060310K0FKEA" 0603 4227.01,2451.39 r90 bottom value=10.0k
R65 "ERJ-2GE0R00X" 0402 3737.74,2756.39 r0 top value=0
R66 "ERJ-2GE0R00X" 0402 3737.74,2711.39 r0 top value=0
R67 "ERJ-2GE0R00X" 0402 3737.74,2666.39 r0 top value=0
R68 "ERJ-2GE0R00X" 0402 3737.74,2621.39 r0 top value=0
R69 "ERJ-2GE0R00X" 0402 3737.74,2576.39 r0 top value=0
R70 "ERJ-2GE0R00X" 0402 3737.74,2531.39 r0 top value=0
R71 "ERJ-2GE0R00X" 0402 3737.74,2486.39 r0 top value=0
R72 "ERJ-2GE0R00X" 0402 3737.74,2441.39 r0 top value=0
R73 "ERJ-2GE0R00X" 0402 3737.74,2396.39 r0 top value=0
R74 "ERJ-2GE0R00X" 0402 3737.74,2351.39 r0 top value=0
R75 "ERJ-2GE0R00X" 0402 3737.74,2306.39 r0 top value=0
R76 "ERJ-2GE0R00X" 0402 3730.03,1116.69 r0 top value=0
R77 "ERJ-2GE0R00X" 0402 3730.03,1071.69 r0 top value=0
R78 "ERJ-2GE0R00X" 0402 3730.03,1026.69 r0 top value=0
R79 "ERJ-2GE0R00X" 0402 3730.03,981.69 r0 top value=0
R80 "ERJ-2GE0R00X" 0402 3730.03,936.69 r0 top value=0
R81 "ERJ-2GE0R00X" 0402 3730.03,891.69 r0 top value=0
R82 "ERJ-2GE0R00X" 0402 3730.03,846.69 r0 top value=0
R83 "ERJ-2GE0R00X" 0402 3730.03,801.69 r0 top value=0
R84 "ERJ-2GE0R00X" 0402 3730.03,756.69 r0 top value=0
R85 "ERJ-2GE0R00X" 0402 3730.03,711.69 r0 top value=0
R86 "ERJ-2GE0R00X" 0402 3730.03,666.69 r0 top value=0
R87 "CRCW060310K0FKEA" 0603 4220.03,766.7 r90 bottom value=10.0k
R88 "CRCW04024K70JNED" 0402 2960,1514.75 r90 top value=4.7k
R89 "CRCW04024K70JNED" 0402 3005,1514.75 r90 top value=4.7k
R90 "CRCW04024K70JNED" 0402 3080,1589.75 r180 top value=4.7k
R91 "CRCW04024K70JNED" 0402 2985,1589.75 r0 top value=4.7k
R92 "CRCW0402100RJNED" 0402 3040,1969.75 r0 top value=100
R95 "CRCW040233R0JNED" 0402 3265,2199.75 r0 top value=33
R97 "RG1608P-102-B-T5" 0603 676,2197 r270 top value=1.00k
R98 "RG1608P-102-B-T5" 0603 676,2497 r270 top value=1.00k
R99 "CRCW0603249RFKEA" 0603 1270,2254.75 r270 top value=249
R100 "RT0603BRB071KL" 0603 1715,2249.75 r270 top value=1.00k
R101 "RT0603BRB071KL" 0603 1715,2379.75 r90 top value=1.00k
R103 "RT0603BRD0720RL" 0603 1805,2279.75 r0 top value=20.0
R104 "RT0603BRD0720RL" 0603 1805,2349.75 r0 top value=20.0
R107 "RG1608P-102-B-T5" 0603 676,1000 r270 top value=1.00k
R108 "RG1608P-102-B-T5" 0603 675.7,1237 r90 top value=1.00k
R110 "RG1608P-102-B-T5" 0603 1170,904.75 r0 bottom value=1.00k
R112 "RC0603FR-07124RL" 0603 1235,1394.75 r180 top value=124
R113 "RC0603FR-07124RL" 0603 1235,1069.75 r180 top value=124
R114 "RT0603BRB071KL" 0603 1355,1069.75 r0 top value=1.00k
R115 "RT0603BRD0720RL" 0603 1475,1014.75 r0 top value=20.0
R116 "RT0603BRB071KL" 0603 1355,1394.75 r0 top value=1.00k
R117 "RT0603BRD0720RL" 0603 1475,1339.75 r0 top value=20.0
R211 "ERJ-2GE0R00X" 0402 1575,2289.75 r0 top value=0
R212 "ERJ-2GE0R00X" 0402 1575,2339.75 r0 top value=0
R213 "ERJ-2GE0R00X" 0402 1170,959.75 r0 bottom value=0
R214 "RG1608P-102-B-T5" 0603 1220,1682.38 r180 top value=1.00k
R215 "RG1608P-4990-B-T5" 0603 1125,1707.38 r270 top value=499
R216 "RG1608P-203-B-T5" 0603 1030,1682.38 r0 top value=20.0k
R217 "RG1608P-4992-B-T5" 0603 1180,1852.38 r90 top value=49.9k
R218 "RG1608P-4992-B-T5" 0603 1235,1852.38 r270 top value=49.9k
R223 "ERJ-2GE0R00X" 0402 2075,874.75 r0 top value=0
R225 "ERJ-2GE0R00X" 0402 2075,1054.75 r0 top value=0
R226 "ERJ-2GE0R00X" 0402 2075,1145 r0 top value=0
R232 "ERJ-2GE0R00X" 0402 2335,2169.75 r0 top value=0
R233 "ERJ-2GE0R00X" 0402 2335,2214.75 r0 top value=0
R234 "ERJ-2GE0R00X" 0402 2335,2259.75 r0 top value=0
R235 "ERJ-2GE0R00X" 0402 2335,2304.75 r0 top value=0
R240 "ERJ-2GE0R00X" 0402 2075,1009.75 r0 top value=0
R246 "RG1608P-4992-B-T5" 0603 2785,3305 r90 top value=49.9k
R247 "RG1608P-4992-B-T5" 0603 2040,3114.02 r90 top value=49.9k
R248 "ERJ-2GE0R00X" 0402 1480,2454.75 r0 top value=0
R250 "ERJ-2GE0R00X" 0402 1395,934.75 r270 bottom value=0
R252 "ERJ-2GE0R00X" 0402 1394.48,1244.01 r270 bottom value=0
R255 "ERJ-2GE0R00X" 0402 1995,1654.75 r180 top value=0
R256 "CRCW040233R0JNED" 0402 3265,2149.75 r0 top value=33
R257 "CRCW040233R0JNED" 0402 3265,2094.75 r0 top value=33
R258 "RG1608P-103-B-T5" 0603 2125,2614.75 r0 top value=10.0k
R259 "ERJ-2GE0R00X" 0402 2130,2664.75 r0 top value=0
R260 "ERJ-2GE0R00X" 0402 2130,2709.75 r0 top value=0
R261 "RG1608P-103-B-T5" 0603 1885,1479.75 r0 top value=10.0k
R262 "ERJ-2GE0R00X" 0402 1890,1529.75 r180 top value=0
R263 "ERJ-2GE0R00X" 0402 1890,1574.75 r180 top value=0
R268 "CRCW06031R00FKEA" 0603 1935,2514.75 r90 top value=1.00
R269 "CRCW06031R00FKEA" 0603 1710,1359.75 r90 top value=1.00
R278 "CRCW040233R0JNED" 0402 3265,2044.75 r0 top value=33
R279 "ERJ-2GE0R00X" 0402 4122.01,2406.39 r0 bottom value=0
R280 "ERJ-2GE0R00X" 0402 4130.02,731.69 r0 bottom value=0
R284 "ERJ-2GE0R00X" 0402 1915,2429.75 r0 top value=0
R288 "ERJ-2GE0R00X" 0402 1690,1274.75 r0 top value=0
R290 "CRCW040236K0JNED" 0402 920,270 r270 bottom value=36k
R291 "CRCW0402100KFKED" 0402 865,165 r90 bottom value=100k
R294 "CRCW040222K6FKED" 0402 3745,3665 r90 bottom value=20.5k
R295 "CRCW0402100KFKED" 0402 3800,3770 r270 bottom value=100k
R297 "PCF0402-12-5K62BT1" 0402 745,3005 r270 bottom value=5.62k
R298 "CRCW0402100KFKED" 0402 705,2900 r90 bottom value=100k
R401 "RT0603BRD0758K3L" 0603 2355,3410 r180 bottom value=58.3k
R402 "RC0603FR-071ML" 0603 2180,3430 r180 bottom value=1.00Meg
R404 "CRCW060380K6FKEA" 0603 2500,3395 r0 bottom value=80.6k
R453 "ERJ-2GE0R00X" 0402 675,1629.75 r270 top value=0
R454 "ERJ-2GE0R00X" 0402 720,1629.75 r270 top value=0
R457 "ERJ-2GE0R00X" 0402 495,1979.75 r0 top value=0
R485 "RG1608P-102-B-T5" 0603 1000,1534.75 r90 top value=1.00k
R486 "RG1608P-2491-B-T5" 0603 810,1629.75 r180 top value=2.49k
R488 "RG1608P-4991-B-T5" 0603 810,1684.75 r180 top value=4.99k
R489 "CRCW06034R75FKEA" 0603 460,1674.75 r180 top value=4.75
R491 "RG1608P-102-B-T5" 0603 459.7,1579.75 r270 top value=1.00k
R492 "RG1608P-4990-B-T5" 0603 349.7,1580 r90 top value=499
R494 "RG1608P-303-B-T5" 0603 289.7,1580 r90 top value=30.0k
RB3 "ERJ-2GE0R00X" 0402 910,480 r90 bottom value=0
RB5 "ERJ-2GE0R00X" 0402 3755,3455 r270 bottom value=0
RB18 "ERJ-2GE0R00X" 0402 750,3215 r90 bottom value=0
RDN1 "ERJ-3GEY0R00V" 0603 1120,2464.75 r0 top value=0
RDN2 "RT0603BRB071KL" 0603 1240,2464.75 r180 top value=1.00k
RDN3 "ERJ-3GEY0R00V" 0603 1114.69,1264.75 r0 top value=0
RDN4 "RT0603BRB071KL" 0603 1235,1281 r180 top value=1.00k
RDP1 "ERJ-3GEY0R00V" 0603 1120,2164.75 r0 top value=0
RDP2 "RT0603BRB071KL" 0603 1241,2165 r180 top value=1.00k
RDP3 "ERJ-3GEY0R00V" 0603 1115,959.75 r0 top value=0
RDP4 "RT0603BRB071KL" 0603 1235,959.75 r180 top value=1.00k
REN0 "ERJ-2GE0R00X" 0402 1380,779.75 r180 top value=0
REN1 "ERJ-2GE0R00X" 0402 1375,1119.75 r180 top value=0
Renb "CRCW080520K5FKEA" 0805_HV 930,2850 r180 top value=20.5k
Renb2 "RG1608P-3571-B-T5" 0603 3080,3705 r0 top value=3.57k
Renb3 "RG1608P-3571-B-T5" 0603 2246,624 r0 top value=3.57k
Rent "RT0805BRD07118KL" 0805_HV 775,2850 r180 top value=118k
Rent2 "RT0603BRD0768K1L" 0603 3200,3705 r0 top value=68.1k
Rent3 "RT0603BRD0768K1L" 0603 2375,625 r0 top value=68.1k
RES3V "RG1608P-104-B-T5" 0603 980,225 r90 bottom value=100k
RES5V "RG1608P-104-B-T5" 0603 3685,3710 r270 bottom value=100k
RES18V "RG1608P-104-B-T5" 0603 820,2960 r90 bottom value=100k
Rfbb "RG1608P-152-B-T5" 0603 880,3120 r90 top value=1.50k
Rfbb3 "RT0805BRD071K07L" 0805_HV 2312,246 r0 top value=1.07k
Rfbb5 "RT0805BRD071K07L" 0805_HV 3095,3500 r270 top value=1.07k
Rfbt "RT0603BRD0734KL" 0603 815,3245 r90 top value=34.0k
Rfbt2 "CPF0603B6K34E" 0603 3280,3400 r0 top value=6.34k
Rfbt3 "RG1608P-4021-B-T5" 0603 2455,245 r0 top value=4.02k
RMFBN "ERJ-2GE0R00X" 0402 1233,2520.55 r0 top value=0
RMFBN2 "ERJ-2GE0R00X" 0402 1331,2491 r90 top value=0
RMFBP "ERJ-2GE0R00X" 0402 1233,2110 r180 top value=0
RMFBP2 "ERJ-2GE0R00X" 0402 1329,2138 r90 top value=0
Ron "RT0603BRD07383KL" 0603 800,2980 r270 top value=383k
Ron2 "RT0603BRD07113KL" 0603 3285,3660 r180 top value=113k
Ron3 "RT0603BRD0778K7L" 0603 2484,578 r90 top value=78.7k
RR413 "ERJ-3RQFR22V" 0603 1680,1541 r0 top value=0.22
RR457 "ERJ-2GE0R00X" 0402 1945,1709 r180 top value=0
TP1 "Pogo Pad" PogoPad 2400,2484.75 r0 top
TP2 "Pogo Pad" PogoPad 3125,2515.04 r0 top
TP3 "5015" Testpoint_Keystone_Miniature 1850,3250 r0 top
TP4 "Pogo Pad" PogoPad 2540,1099.75 r0 top
TP7 "Pogo Pad" PogoPad 2867.81,2298.54 r0 top
TP8 "5015" Testpoint_Keystone_Miniature 1400,1949.75 r270 top
TP16 "Pogo Pad" PogoPad 3385,2259.75 r0 top
TP25 "5015" Testpoint_Keystone_Miniature 2215,3030 r0 top
TP26 "5015" Testpoint_Keystone_Miniature 2670,3173.05 r180 top
TP27 "5015" Testpoint_Keystone_Miniature 3050,785 r0 top
TP28 "5015" Testpoint_Keystone_Miniature 1180,1970 r0 top
TP29 "5015" Testpoint_Keystone_Miniature 1180,1582.38 r0 top
TP30 "5015" Testpoint_Keystone_Miniature 1115,819.75 r180 bottom
TP31 "Pogo Pad" PogoPad 3385,2169.75 r0 top
TP32 "Pogo Pad" PogoPad 3385,2069.75 r0 top
TP33 "Pogo Pad" PogoPad 3385,1969.75 r0 top
TP34 "Pogo Pad" PogoPad 2720,1439.75 r90 top
TP35 "Pogo Pad" PogoPad 2460.3,1166.28 r90 top
TP_3P3V "5015" Testpoint_Keystone_Miniature 2130,325 r90 top
TP_3P8V "5015" Testpoint_Keystone_Miniature 1656,221 r90 top
TP_5P5V "5015" Testpoint_Keystone_Miniature 2915,3454.51 r90 top
TP_18P5V "5015" Testpoint_Keystone_Miniature 1621,3233 r0 top
TPAGND "Pogo Pad" PogoPad 2065,1859.75 r90 top locked
TPAGND1 "5015" Testpoint_Keystone_Miniature 1625,2692.75 r0 top
TPAGND2 "5015" Testpoint_Keystone_Miniature 2160,1768.75 r270 top
TPAGND3 "5015" Testpoint_Keystone_Miniature 990,1949.75 r180 top
TPAGND4 "5015" Testpoint_Keystone_Miniature 1116.5,819.75 r0 top
TPGND "Pogo Pad" PogoPad 2613,1819.75 r90 top
TPGND1 "5015" Testpoint_Keystone_Miniature 3378.02,408 r90 top
TPGND2 "5015" Testpoint_Keystone_Miniature 2450,1779.75 r90 top
TPGND3 "5015" Testpoint_Keystone_Miniature 3540,2990 r180 top
TPGND4 "5015" Testpoint_Keystone_Miniature 3385,1410 r90 top
TPPGOOD "Pogo Pad" PogoPad 2795,3435 r270 bottom
TPV4 "5015" Testpoint_Keystone_Miniature 1810,1684.75 r0 top
U1 "OPA625IDBVR" DBV0006A_N 1355,894.75 r270 top
U2 "OPA625IDBVR" DBV0006A_N 1355,1224.75 r270 top
U3 "REF6050IDGKR" DGK0008A_N 1620,1805.16 r0 top
U3P8V "LMS3635MQRNLRQ1" RNL0022A_NV 1130,355 r270 bottom
U4 "OPA376AIDBVR" DBV0005A_N 995,1835.01 r180 top
U5 "LMZ14202TZX-ADJ/NOPB" TZA07A_V 2793,429 r0 top
U5P5V "LMS3635MQRNLRQ1" RNL0022A_NV 3535,3580 r90 bottom
U6 "TPS7A4700RGWR" RGW0020A 1910,185 r180 bottom
U7 "TPS7A4700RGWR" RGW0020A 2905,2980 r90 bottom
U8 "TPS7A4700RGWR" RGW0020A 1740,3040 r180 bottom
U9 "LM5574MT" MTC16_N 2125,3695 r0 top
U10 "LM7705MM/NOPB" MUA08A_N 3173.02,498 r90 bottom
U11 "TPS7A3001MDGNTEP" DGN0008D_N 2520,3050 r180 bottom
U13 "BR24G32FVT-3AGE2" TSOP65P640X120-8N 4032.01,2506.39 r180 bottom
U14 "BR24G32FVT-3AGE2" TSOP65P640X120-8N 4035.02,831.69 r180 bottom
U15 "LMK61E2-SIAR" SIA0008B 2990,1729.75 r90 top
U18 "SN74AUP1G80DCKR" DCK0005A_N 3097.81,2378.54 r270 top
U18P5V "LMS3635MQRNLRQ1" RNL0022A_NV 970,3090 r270 bottom
U19 "SN74AHC1G04DBVR" DBV0005A_N 2867.81,2428.54 r90 top
U22 "LMZ14201TZX-ADJ/NOPB" TZA07A_V 509,3108 r180 top
U23 "LMZ14203TZ-ADJ/NOPB" TZA07A_V 3605,3560 r0 top
U31 "SN74AUP1G80DCKR" DCK0005A_N 2715.21,1284.75 r270 top
U32 "SN74AHC1G04DBVR" DBV0005A_N 2459.83,1296.28 r90 top
U33 "LMK00804BPW" PW0016A_N 3050,2109.75 r0 top
U401 "LM46001PWPR" PWP0016G_N 2405,3550 r180 bottom
U414 "OPA378AIDBVT" DBV0005A_N 830,1529.75 r180 top
U415 "OPA625IDBVR" DBV0006A_N 570,1579.75 r0 top
U422 "REF5040AIDGKT" DGK0008A_N 1558,1637 r0 top
UADS1 "ADS8900BRGER" RGE0024H 2060,2314.75 r270 top
UADS2 "ADS8900BRGER" RGE0024H 1835,1164.75 r270 top
ZZ2 "These assemblies are ESD sensitive, ESD precautions shall be observed." AssemblyNote 300,4700 r0 top
ZZ3 "These assemblies must be clean and free from flux and all contaminants. Use of no clean flux is not acceptable." AssemblyNote 300,4600 r0 top
ZZ4 "These assemblies must comply with workmanship standards IPC-A-610 Class 2, unless otherwise specified." AssemblyNote 300,4500 r0 top

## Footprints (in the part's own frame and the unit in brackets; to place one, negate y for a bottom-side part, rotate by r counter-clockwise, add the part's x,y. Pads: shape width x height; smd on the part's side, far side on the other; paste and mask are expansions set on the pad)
0402 [mm] "0402 from SM-752 data"
  rect 0.8x0.6 smd: 1(-0.6,0) 2(0.6,0)
  silkscreen extent -1.22,-0.52 1.22,0.52, body extent -0.55,-0.3 0.55,0.3, height 0.6
0603 [mm] "0603 from SM-752 data"
  rect 1x0.95 smd: 1(-0.8,0) 2(0.8,0)
  silkscreen extent -1.52,-0.69 1.52,0.69, body extent -0.87,-0.47 0.87,0.47, height 1
0603_120#1 [mm] "0603_120"
  rect 1x1 smd: 1(-0.8,0) 2(0.8,0)
  silkscreen extent -0.1,-0.58 0.1,0.58, body extent -0.87,-0.48 0.87,0.48, height 1.2
0603_120#2 [mm] "0603_120"
  rect 1x1 smd: 1(-0.8,0.127) 2(0.8,0.127)
  silkscreen extent -0.1,-0.45 0.1,0.7, body extent -0.87,-0.35 0.87,0.6, height 1.2
0805 [mm] "0805 from SM-752 data"
  rect 1.3x1.5 smd: 1(-0.85,0) 2(0.85,0)
  silkscreen extent -1.72,-0.97 1.72,0.97, body extent -1.1,-0.72 1.1,0.72, height 1.45
0805_HV [mil] "0805 with 30mil clearance between pads"
  rect 50x63 smd: 1(-40,0) 2(40,0)
  silkscreen extent -74,-40 74,40, body extent -43,-29 43,29, height 57
1206 [mm] "1206 from SM-752 data"
  rect 1.3x1.85 smd: 1(-1.45,0) 2(1.45,0)
  silkscreen extent -2.4,-1.21 2.4,1.21, body extent -1.7,-0.9 1.7,0.9, height 1.35
1206_180 [mm] "1206_180"
  rect 1.1x1.6 smd: 1(-1.7,0) 2(1.7,0)
  silkscreen extent -0.9,-1 0.9,1, body extent -1.75,-0.95 1.75,0.95, height 1.8
1206_190 [mm] "1206_190"
  rect 1.1x1.6 smd: 1(-1.7,0) 2(1.7,0)
  silkscreen extent -0.9,-1 0.9,1, body extent -1.75,-0.95 1.75,0.95, height 1.9
1210_270 [mm] "1210"
  rect 1.3x2.7 smd: 1(-1.45,0) 2(1.45,0)
  silkscreen extent -2.32,-1.57 2.32,1.57, body extent -1.7,-1.35 1.7,1.35, height 2.7
1210_280 [mm] "SMD, 2-Leads, Body 3.6x2.8mm, Height 2.8mm"
  rect 1.1x2.2 smd: 1(-1.65,0) 2(1.65,0)
  silkscreen extent -0.84,-1.4 0.84,1.4, body extent -1.8,-1.4 1.8,1.4, height 2.8
6032-28 [mm] "Medium Density IPC based on Vishay Sprague 293D datasheet."
  rect 2.55x2.3 smd: 1(-2.375,0) 2(2.375,0)
  silkscreen extent -3.96,-1.75 3.2,1.83, body extent -3.15,-1.75 3.15,1.75, height 2.8
Amphenol_901-144-8RFX [mm] "SMA Straight Jack, TH"
  round 2 hole 1.5: 1(0,0)
  round 2.2 hole 1.7: 2(-2.54,2.54) 3(-2.54,-2.54) 4(2.54,-2.54) 5(2.54,2.54)
  silkscreen extent -3.7,-3.7 3.7,3.7, body extent -3.7,-3.7 3.7,3.7, height 9.93
AssemblyNote [mil] "Assembly Note"
D0008A_N [mm] "SOIC, 8-Leads, Body 4.9x3.9mm, Pitch 1.27mm, IPC Medium Density"
  oval 1.45x0.6 smd: 1(-2.725,1.905) 2(-2.725,0.635) 3(-2.725,-0.635) 4(-2.725,-1.905) 5(2.725,-1.905) 6(2.725,-0.635) 7(2.725,0.635) 8(2.725,1.905)
  silkscreen extent -3.3,-2.5 0.9,2.5, body extent -3,-2.45 3,2.45, height 1.63
DBV0005A_N [mm] "SOT23, 5-Leads, Body 2.9x1.6mm, Pitch 0.95mm, Lead Span 2.8mm, IPC Medium Density"
  rrect17% 1x0.6 smd: 1(-1.375,0.95) 2(-1.375,0) 3(-1.375,-0.95) 4(1.375,-0.95) 5(1.375,0.95)
  silkscreen extent -1.63,-1.55 0.38,1.55, body extent -1.42,-1.46 1.42,1.46, height 1.09
DBV0006A_N [mm] "SOT23, 6-Leads, Body 2.9x1.6mm, Pitch 0.95mm, Lead Span 2.8mm, IPC Medium Density"
  rrect17% 1x0.6 smd: 1(-1.375,0.95) 2(-1.375,0) 3(-1.375,-0.95) 4(1.375,-0.95) 5(1.375,0) 6(1.375,0.95)
  silkscreen extent -1.68,-1.55 0.5,1.55, body extent -1.42,-1.46 1.42,1.46, height 1.12
DCK0005A_N [mm] "SOT353, 5-Leads, Body 2x1.3mm, Pitch 0.65mm, Lead Span 2.1mm, IPC Medium Density"
  rrect25% 0.85x0.4 smd: 1(-1.125,0.65) 2(-1.125,0) 3(-1.125,-0.65) 4(1.125,-0.65) 5(1.125,0.65)
  silkscreen extent -1.48,-1.02 0.55,1.1, body extent -1.14,-1 1.14,1, height 0.95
